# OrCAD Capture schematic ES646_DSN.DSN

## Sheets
1 INDEX
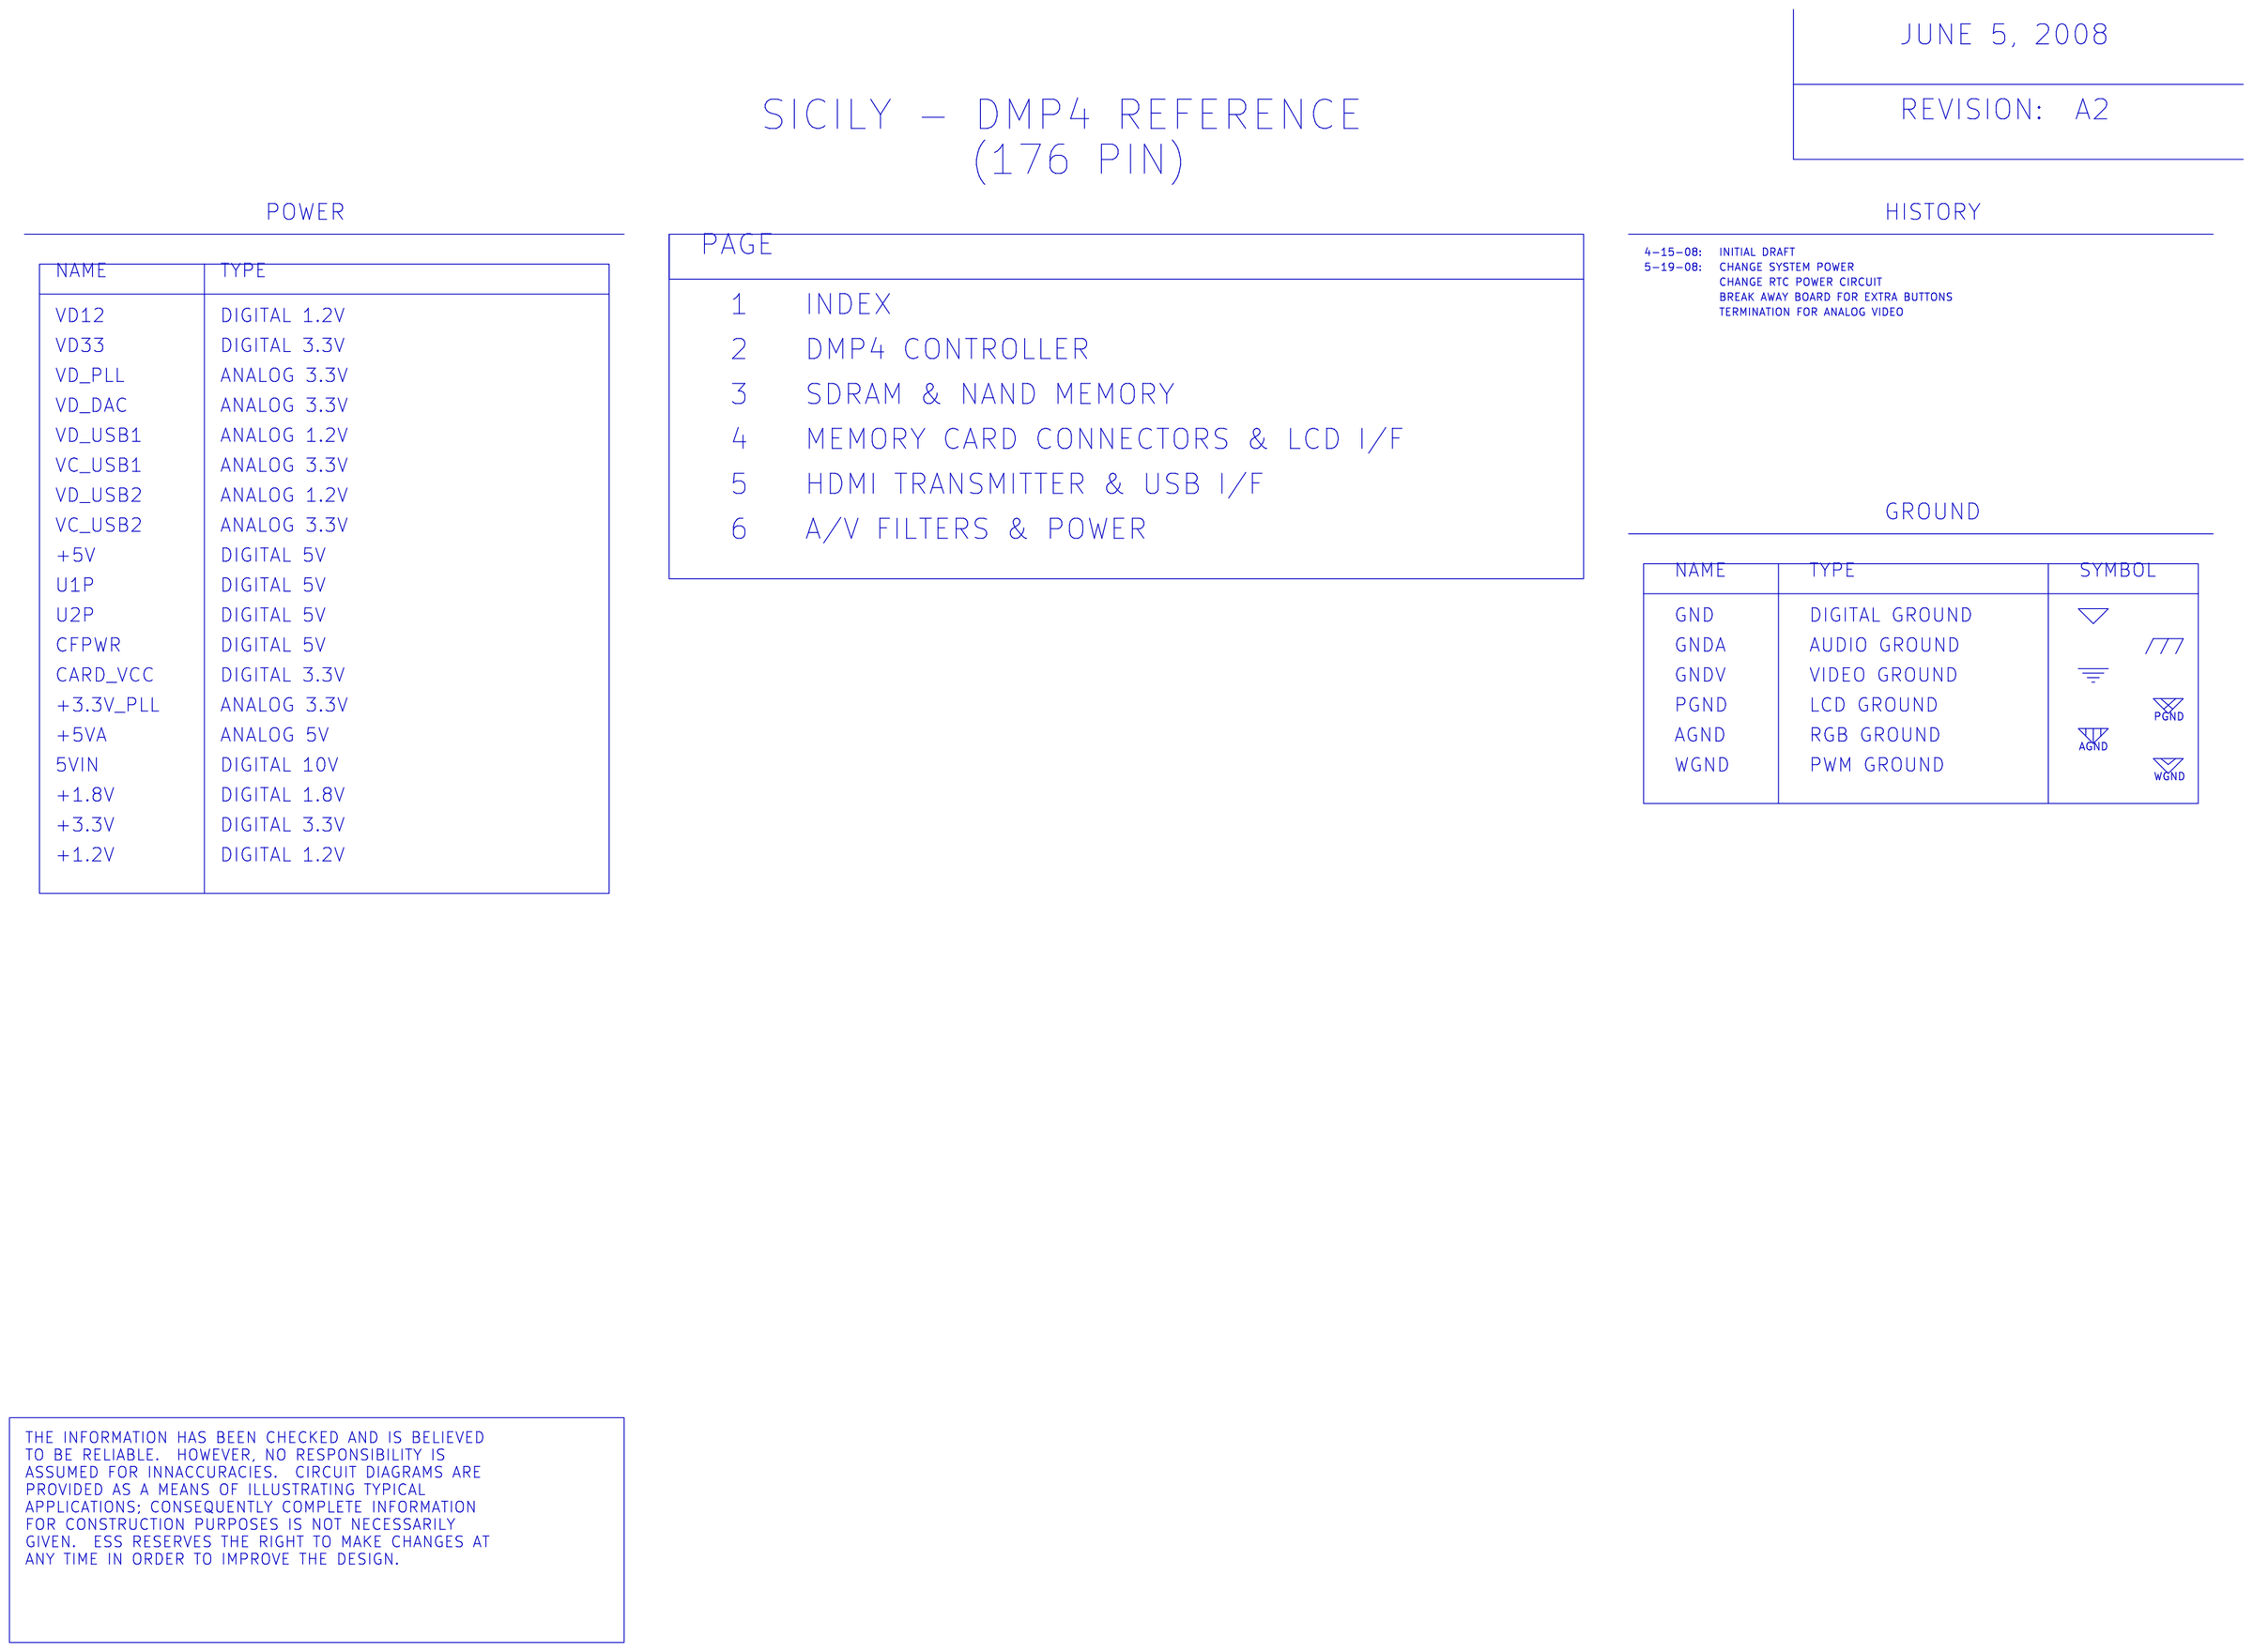
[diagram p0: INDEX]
2 DMP4(ES6461): size Custom
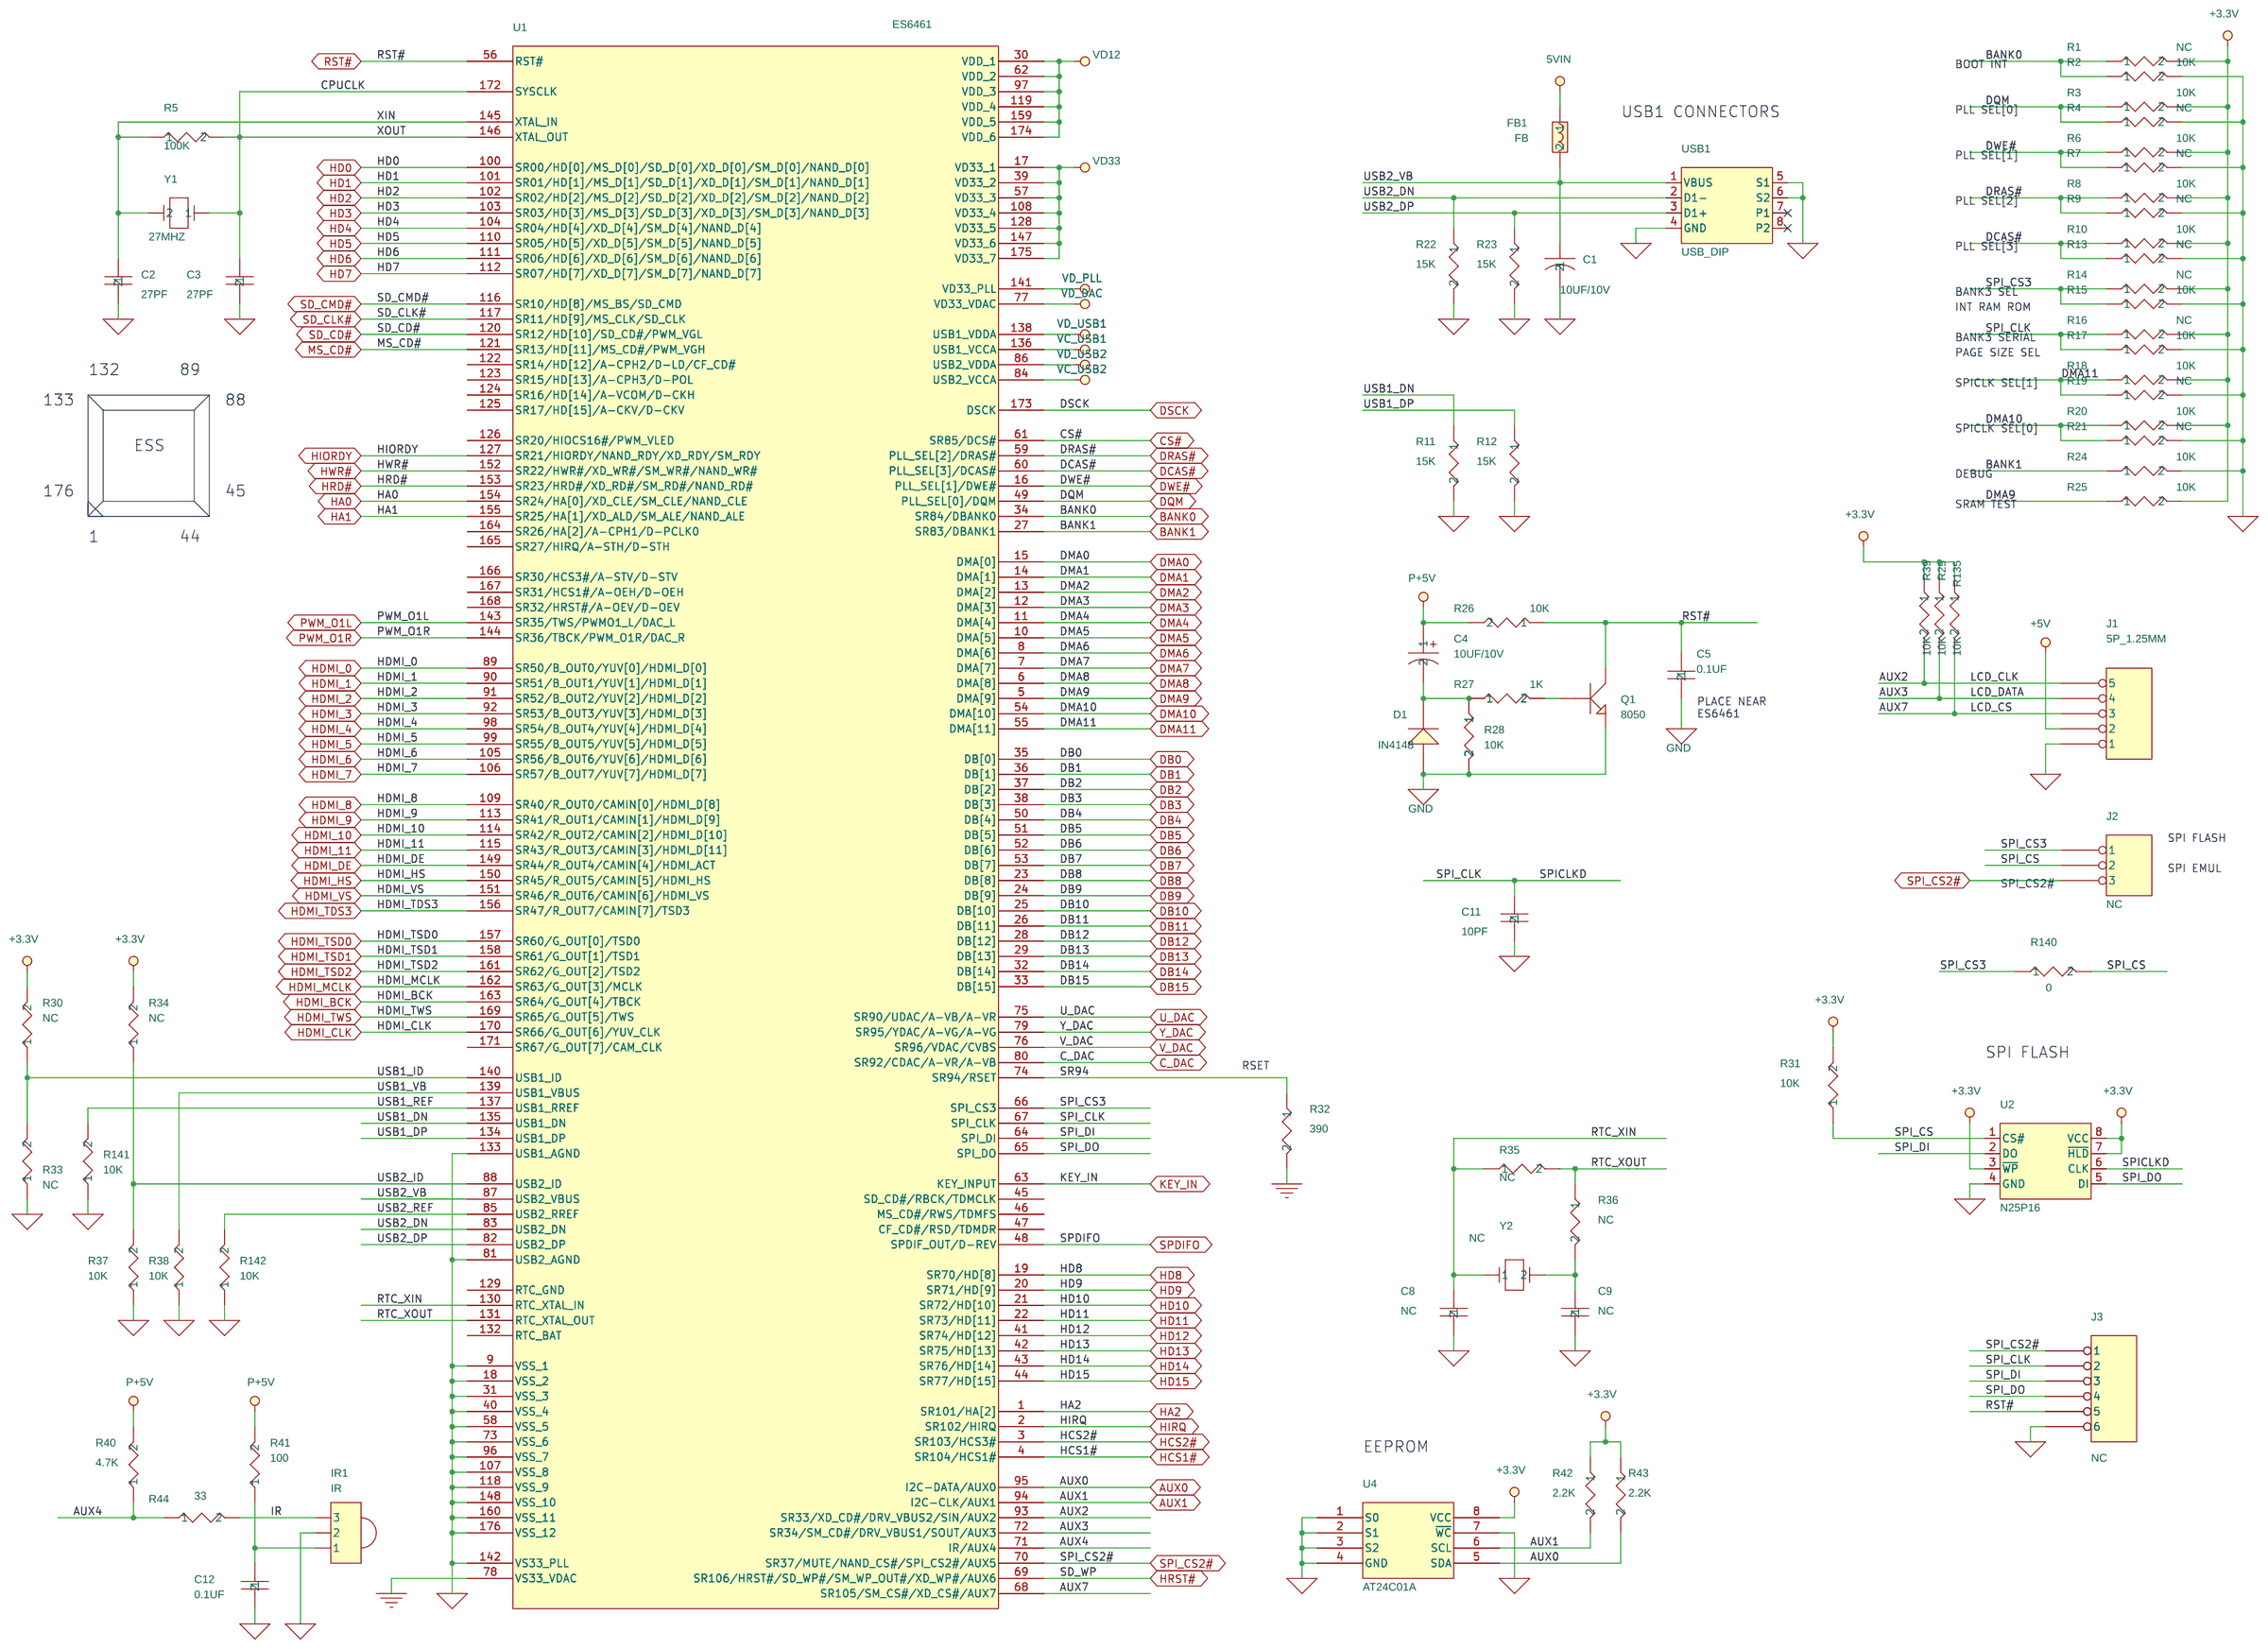
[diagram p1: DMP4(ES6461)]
3 MEMORY/CARD/KEY: size Custom
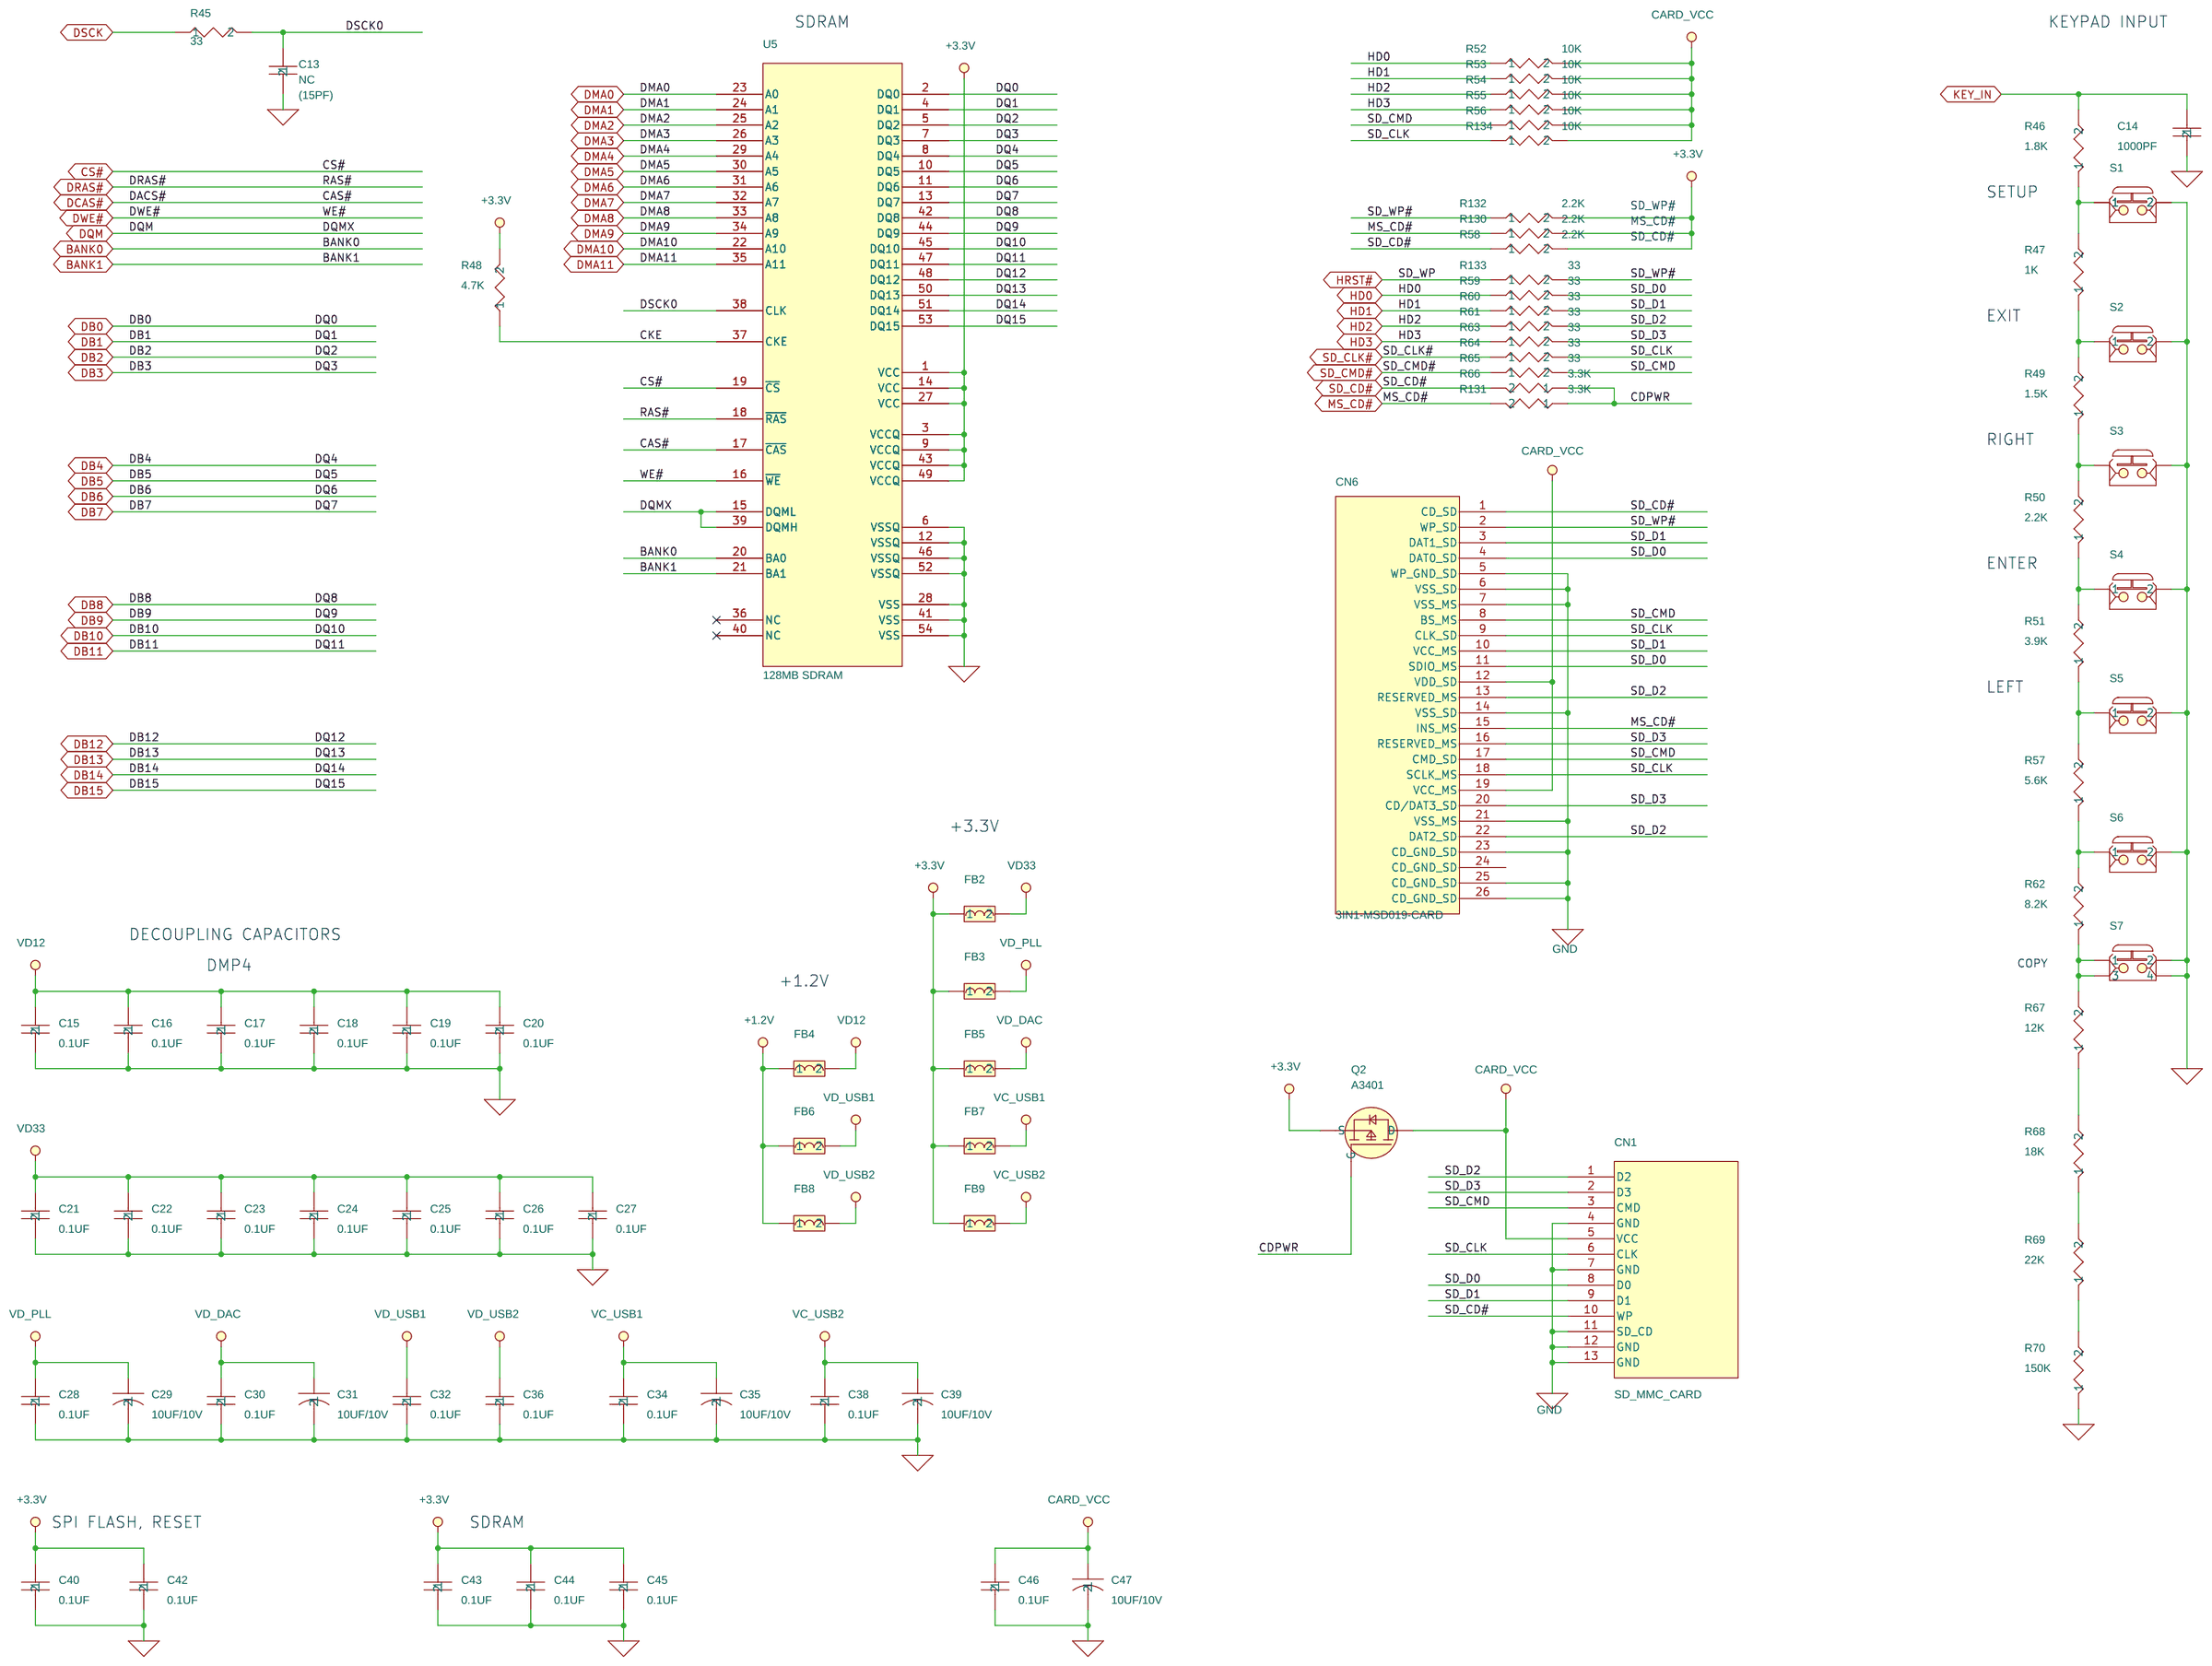
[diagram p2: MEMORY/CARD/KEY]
4 GL830: size B
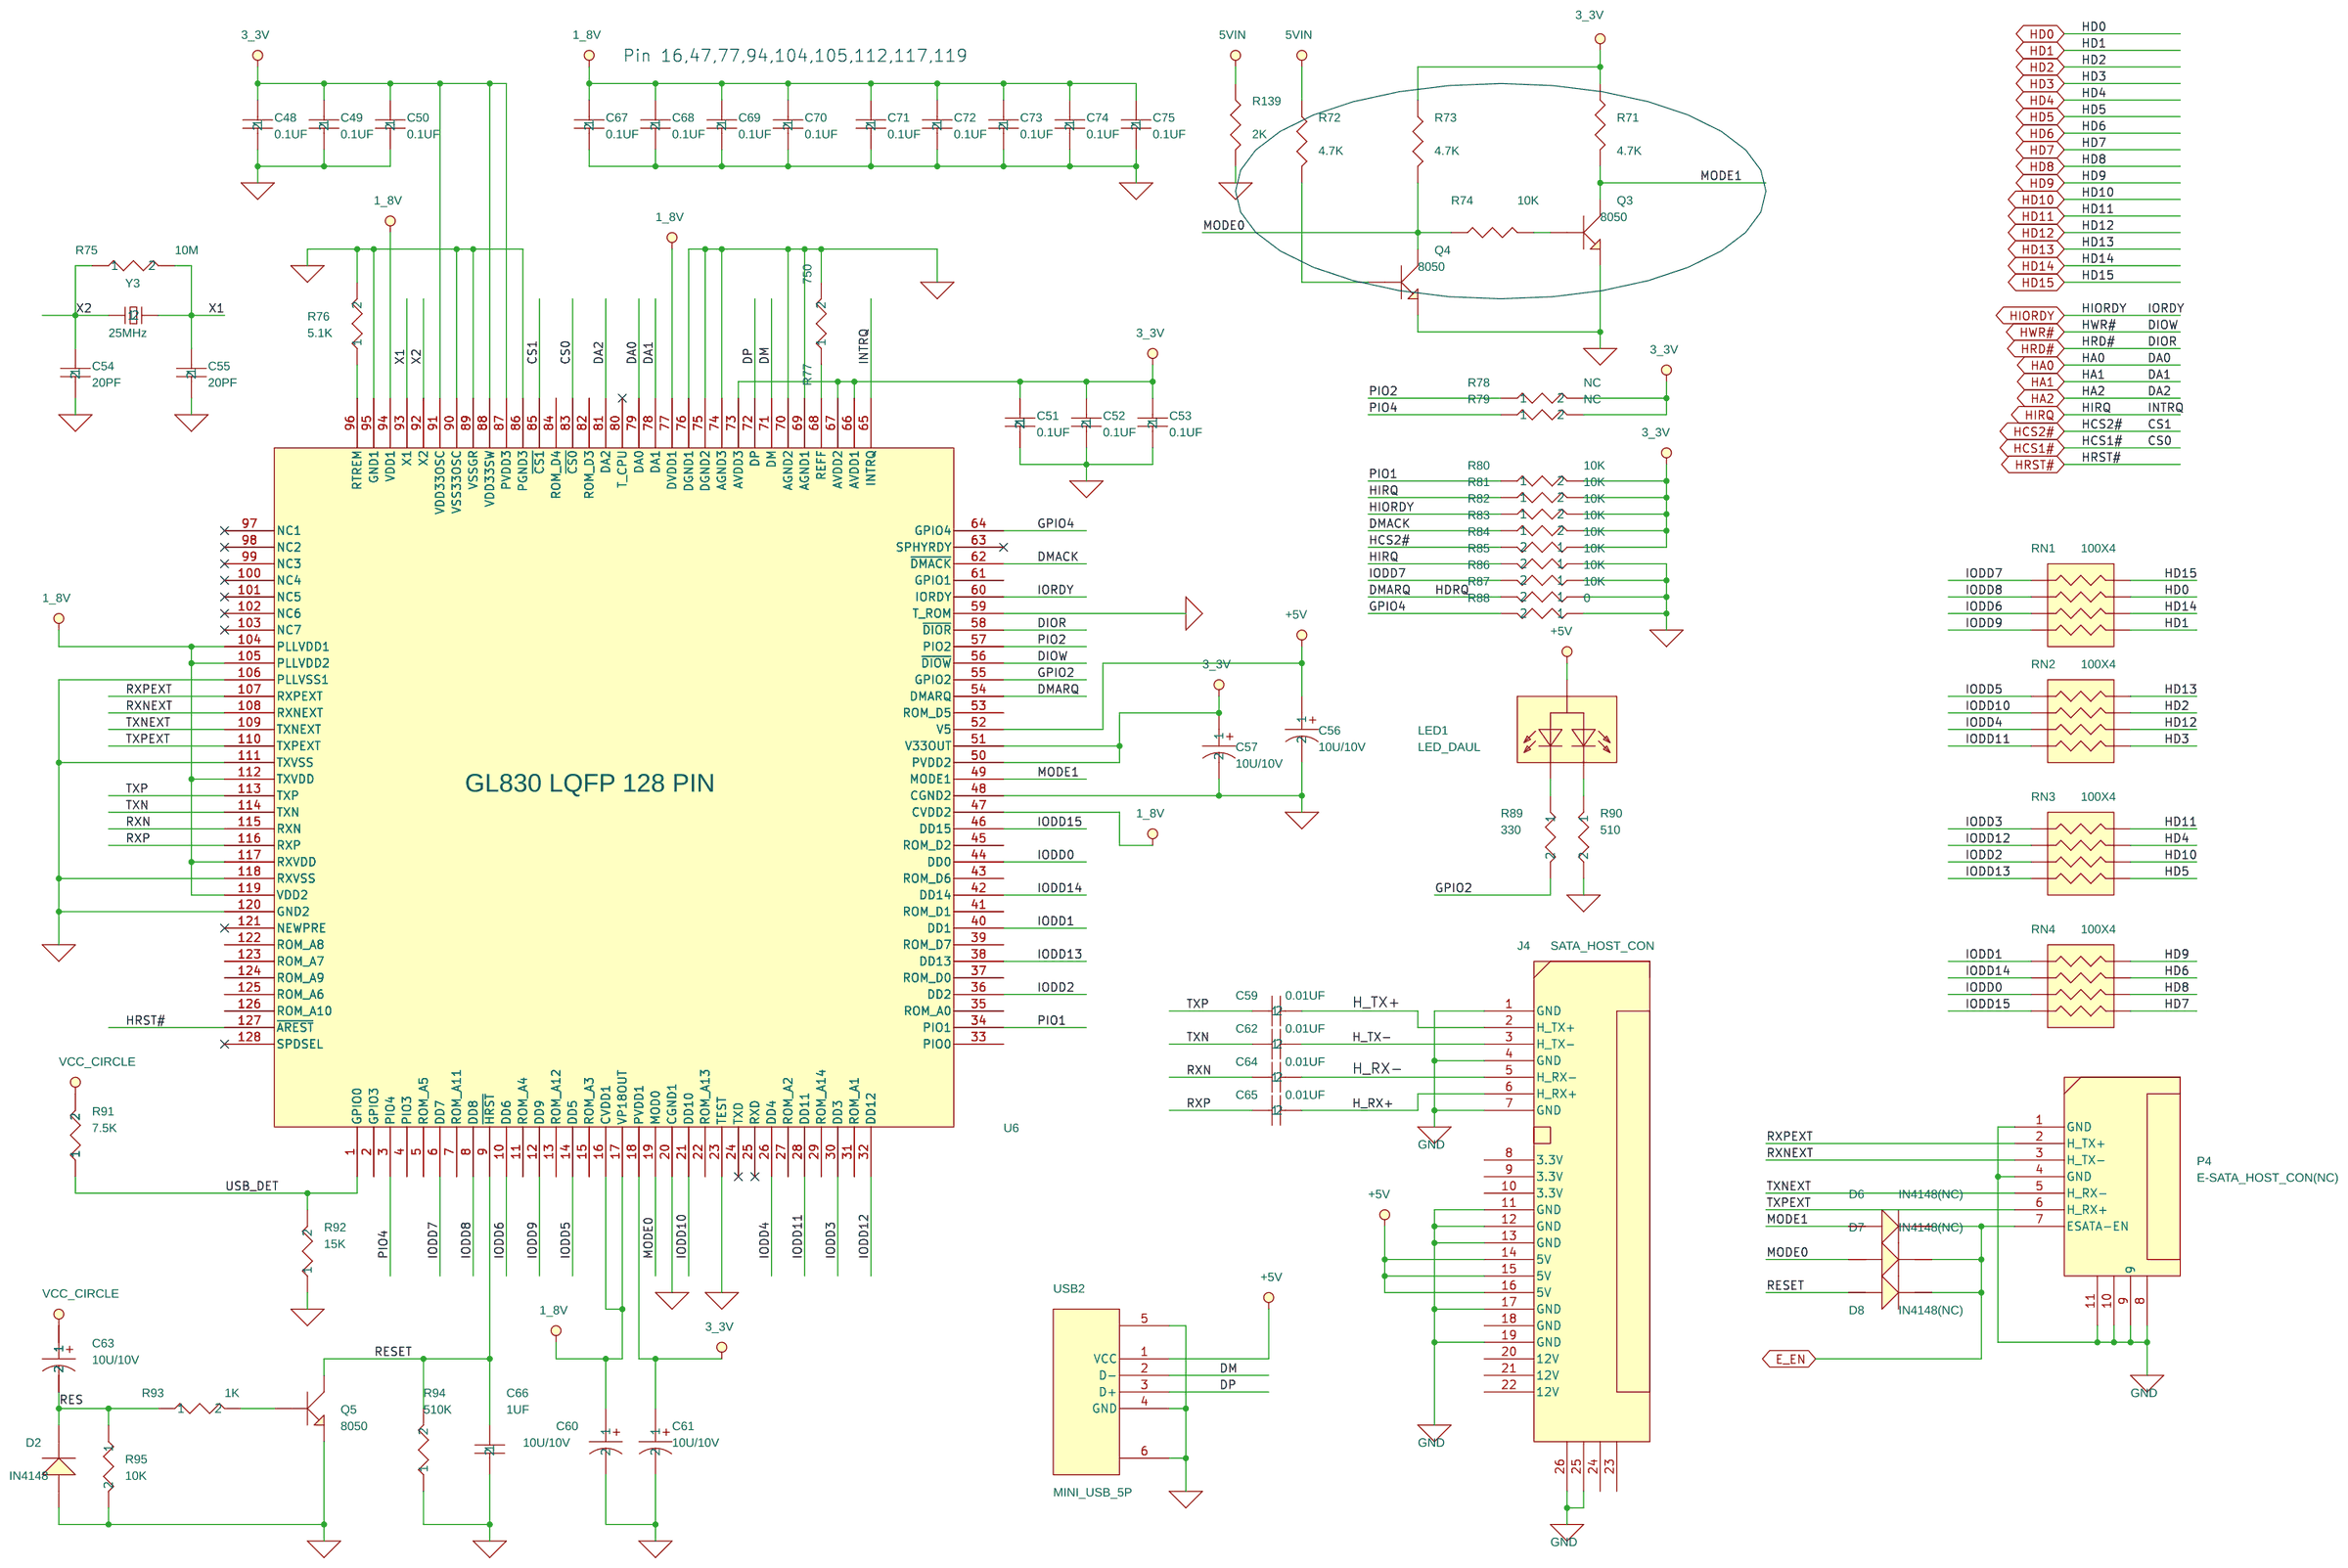
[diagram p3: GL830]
5 HDMI(CKD180): size B
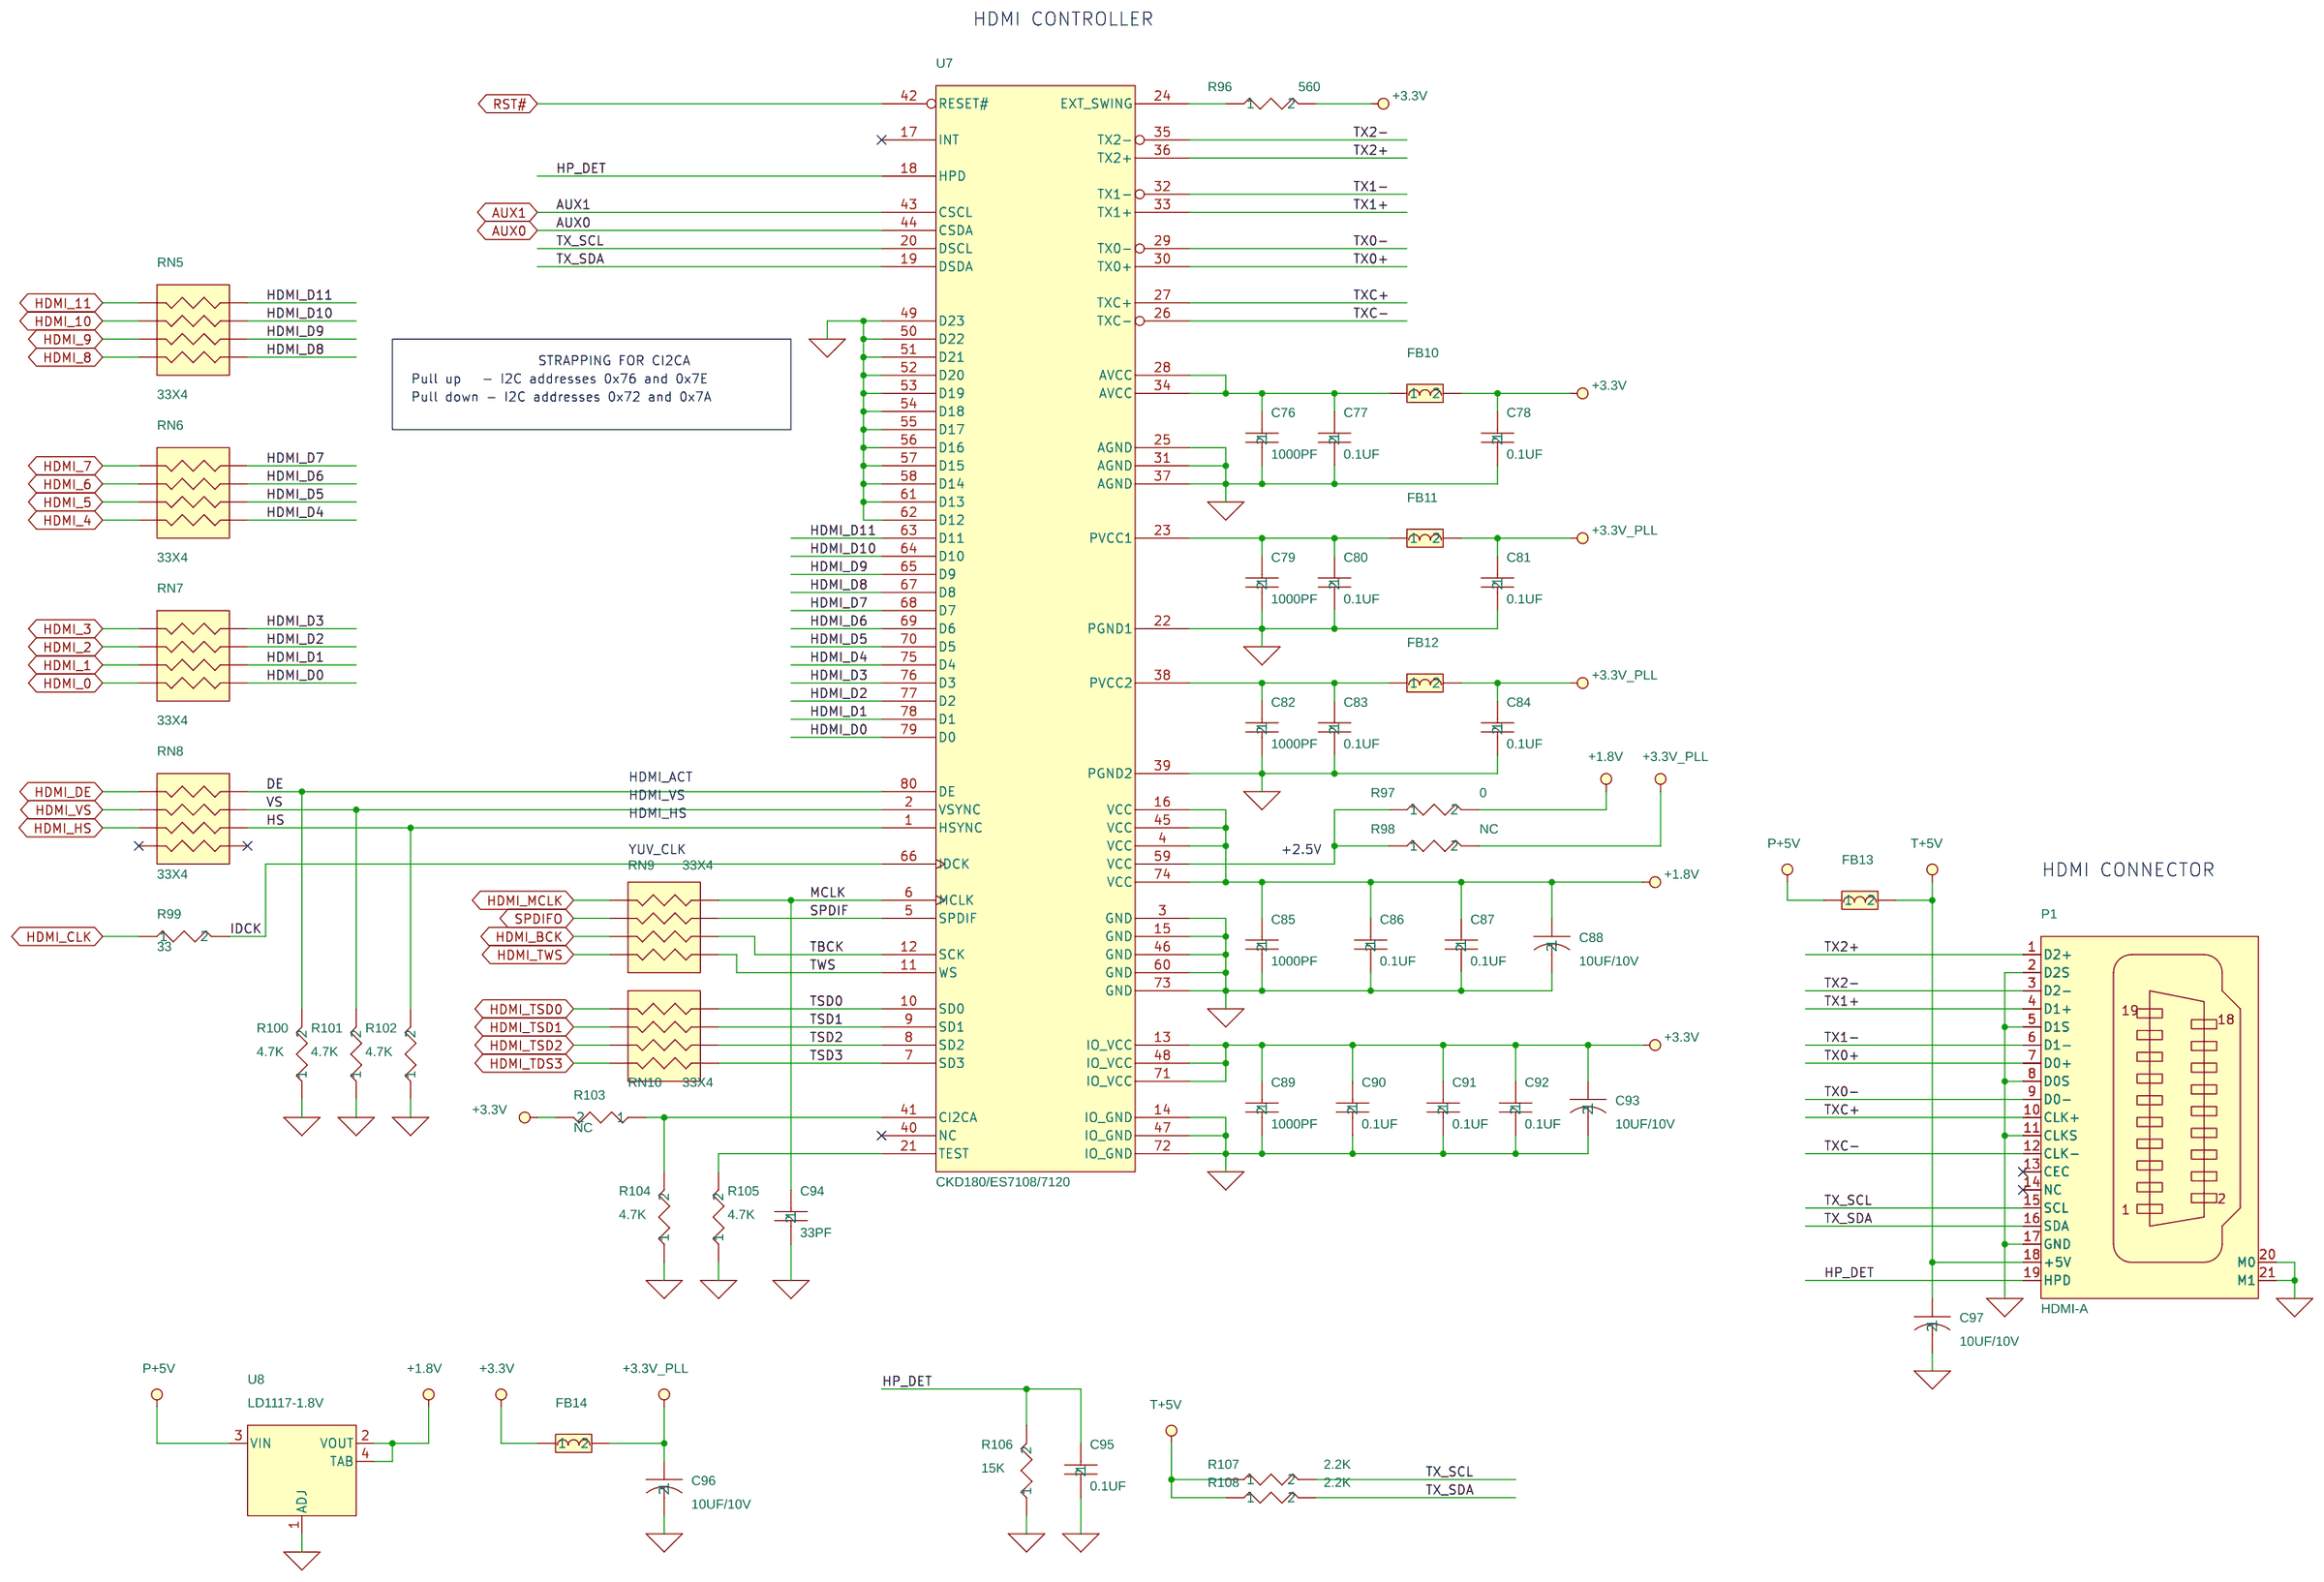
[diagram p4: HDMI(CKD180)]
6 POWER/AV OUT: size Custom
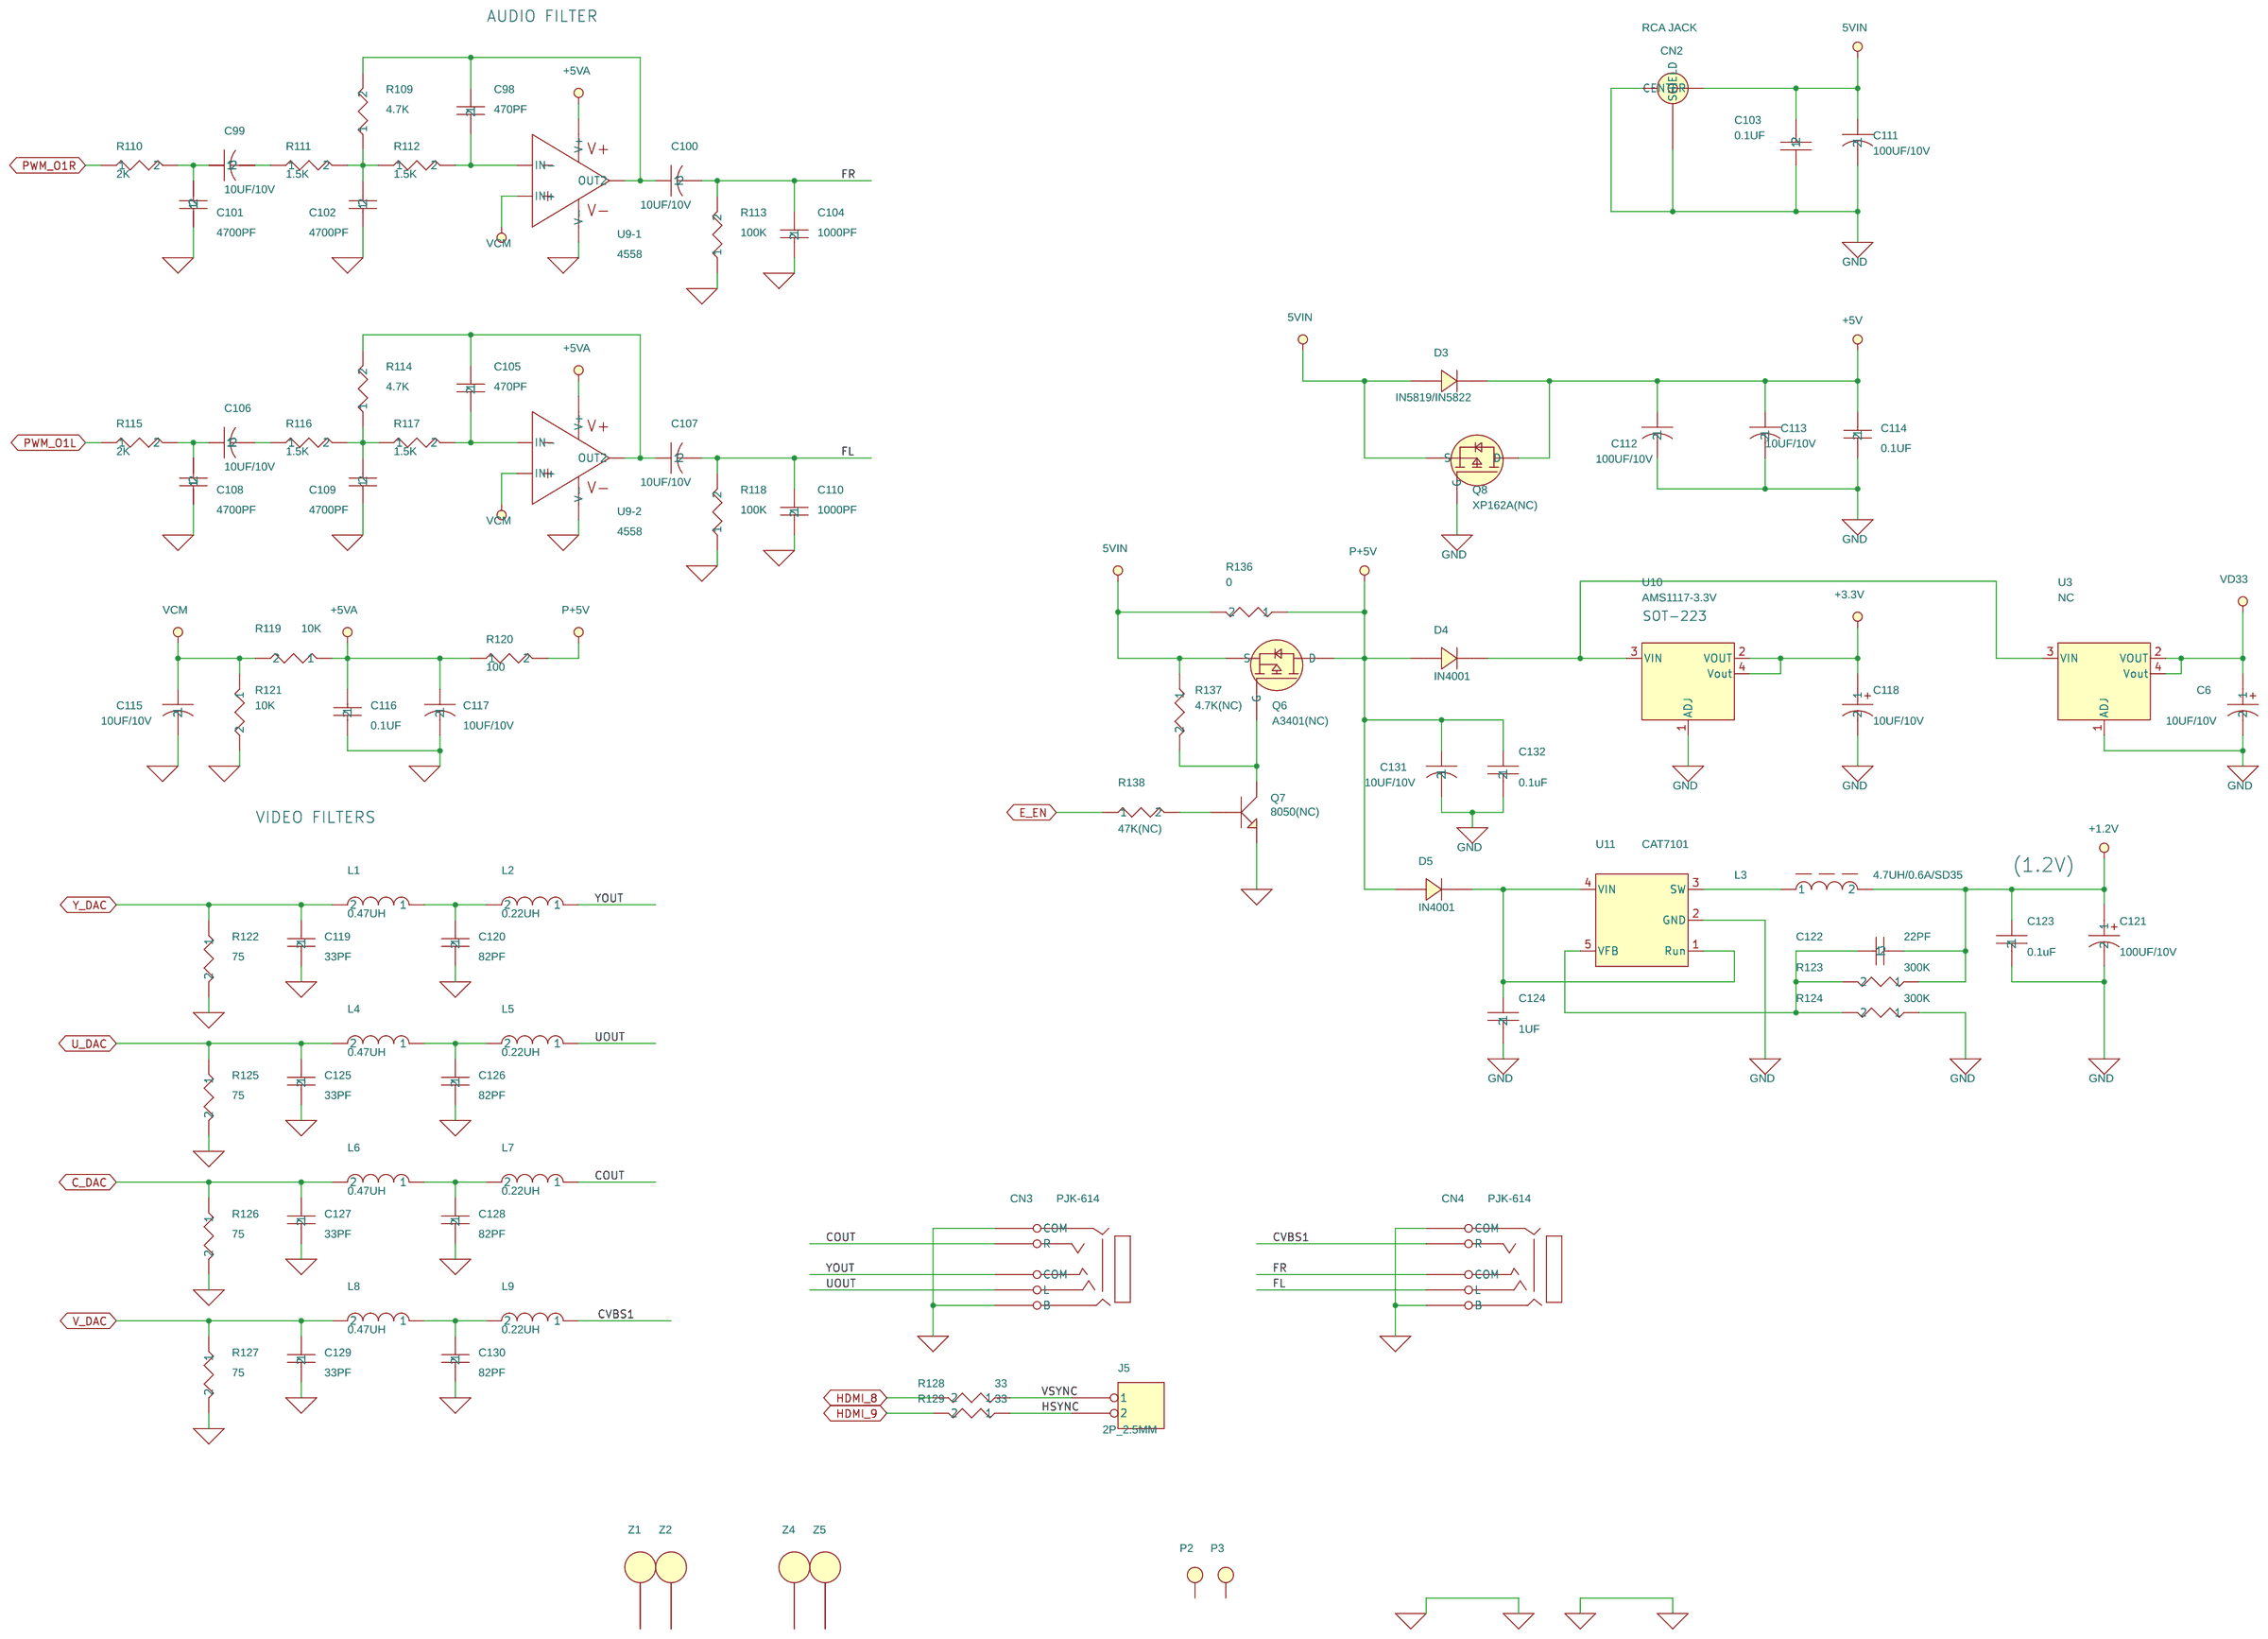
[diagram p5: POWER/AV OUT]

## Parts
sheet DMP4(ES6461)
C1  10UF/10V  [TAJA]
C2  27PF  [0603-CAP]
C3  27PF  [0603-CAP]
C4  10UF/10V  [TAJA]
C5  0.1UF  [0603-CAP]
C8  NC  [0603-CAP]
C9  NC  [0603-CAP]
C11  10PF  [0603-CAP]
C12  0.1UF  [0603-CAP]
D1  IN4148  [IN4148]
FB1  FB  [0603-FBR]
IR1  IR  [IR1]
J1  5P_1.25MM  [CON5/1.25S]
J2  NC  [CON2.0-3]
J3  NC  [CON2.0-6]
Q1  8050  [SOT-23]
R1  NC  [0603-RES]
R2  10K  [0603-RES]
R3  10K  [0603-RES]
R4  NC  [0603-RES]
R5  100K  [0603-RES]
R6  10K  [0603-RES]
R7  NC  [0603-RES]
R8  10K  [0603-RES]
R9  NC  [0603-RES]
R10  10K  [0603-RES]
R11  15K  [0603-RES]
R12  15K  [0603-RES]
R13  NC  [0603-RES]
R14  NC  [0603-RES]
R15  10K  [0603-RES]
R16  NC  [0603-RES]
R17  10K  [0603-RES]
R18  10K  [0603-RES]
R19  NC  [0603-RES]
R20  10K  [0603-RES]
R21  NC  [0603-RES]
R22  15K  [0603-RES]
R23  15K  [0603-RES]
R24  10K  [0603-RES]
R25  10K  [0603-RES]
R26  10K  [0603-RES]
R27  1K  [0603-RES]
R28  10K  [0603-RES]
R29  10K  [0603-RES]
R30  NC  [0603-RES]
R31  10K  [0603-RES]
R32  390  [0603-RES]
R33  NC  [0603-RES]
R34  NC  [0603-RES]
R35  NC  [0603-RES]
R36  NC  [0603-RES]
R37  10K  [0603-RES]
R38  10K  [0603-RES]
R39  10K  [0603-RES]
R40  4.7K  [0603-RES]
R41  100  [0603-RES]
R42  2.2K  [0603-RES]
R43  2.2K  [0603-RES]
R44  33  [0603-RES]
R135  10K  [0603-RES]
R140  0  [0603-RES]
R141  10K  [0603-RES]
R142  10K  [0603-RES]
U1  ES6461  [LQFP176/ES6811]
U2  N25P16  [M25P80]
U4  AT24C01A  [SO-8]
USB1  USB_DIP  [USB-A]
Y1  27MHZ  [HC-49/SM]
Y2  NC  [32.768KHZ-SMT]
sheet GL830
C48  0.1UF  [0603-CAP]
C49  0.1UF  [0603-CAP]
C50  0.1UF  [0603-CAP]
C51  0.1UF  [0603-CAP]
C52  0.1UF  [0603-CAP]
C53  0.1UF  [0603-CAP]
C54  20PF  [0603-CAP]
C55  20PF  [0603-CAP]
C56  10U/10V  [TAJA]
C57  10U/10V  [TAJA]
C59  0.01UF  [0603-CAP]
C60  10U/10V  [TAJA]
C61  10U/10V  [TAJA]
C62  0.01UF  [0603-CAP]
C63  10U/10V  [TAJA]
C64  0.01UF  [0603-CAP]
C65  0.01UF  [0603-CAP]
C66  1UF  [0603-CAP]
C67  0.1UF  [0603-CAP]
C68  0.1UF  [0603-CAP]
C69  0.1UF  [0603-CAP]
C70  0.1UF  [0603-CAP]
C71  0.1UF  [0603-CAP]
C72  0.1UF  [0603-CAP]
C73  0.1UF  [0603-CAP]
C74  0.1UF  [0603-CAP]
C75  0.1UF  [0603-CAP]
D2  IN4148  [IN4148]
D6  IN4148(NC)  [IN4148-LYH]
D7  IN4148(NC)  [IN4148-LYH]
D8  IN4148(NC)  [IN4148-LYH]
J4  SATA_HOST_CON  [SATA2.5HDD-LYH-SMT-A]
LED1  LED_DAUL  [LED2A]
P4  E-SATA_HOST_CON(NC)  [E-SATA-1.27A]
Q3  8050  [SOT23]
Q4  8050  [SOT23]
Q5  8050  [SOT-23]
R71  4.7K  [0603-RES]
R72  4.7K  [0603-RES]
R73  4.7K  [0603-RES]
R74  10K  [0603-RES]
R75  10M  [0603-RES]
R76  5.1K  [0603-RES]
R77  750  [0603-RES]
R78  NC  [0603-RES]
R79  NC  [0603-RES]
R80  10K  [0603-RES]
R81  10K  [0603-RES]
R82  10K  [0603-RES]
R83  10K  [0603-RES]
R84  10K  [0603-RES]
R85  10K  [0603-RES]
R86  10K  [0603-RES]
R87  10K  [0603-RES]
R88  0  [0603-RES]
R89  330  [0603-RES]
R90  510  [0603-RES]
R91  7.5K  [0603-RES]
R92  15K  [0603-RES]
R93  1K  [0603-RES]
R94  510K  [0603-RES]
R95  10K  [0603-RES]
R139  2K  [0603-RES]
RN1  100X4  [RP4-065W-C]
RN2  100X4  [RP4-065W-C]
RN3  100X4  [RP4-065W-C]
RN4  100X4  [RP4-065W-C]
U6  GL830 LQFP 128 PIN  [GL830]
USB2  MINI_USB_5P  [SUBAA]
Y3  25MHz  [HC-49/SM]
sheet HDMI(CKD180)
C76  1000PF  [0603-CAP]
C77  0.1UF  [0603-CAP]
C78  0.1UF  [0603-CAP]
C79  1000PF  [0603-CAP]
C80  0.1UF  [0603-CAP]
C81  0.1UF  [0603-CAP]
C82  1000PF  [0603-CAP]
C83  0.1UF  [0603-CAP]
C84  0.1UF  [0603-CAP]
C85  1000PF  [0603-CAP]
C86  0.1UF  [0603-CAP]
C87  0.1UF  [0603-CAP]
C88  10UF/10V  [TAJA]
C89  1000PF  [0603-CAP]
C90  0.1UF  [0603-CAP]
C91  0.1UF  [0603-CAP]
C92  0.1UF  [0603-CAP]
C93  10UF/10V  [TAJA]
C94  33PF  [0603-CAP]
C95  0.1UF  [0603-CAP]
C96  10UF/10V  [TAJA]
C97  10UF/10V  [TAJA]
FB10  FB  [0603-FBR]
FB11  FB  [0603-FBR]
FB12  FB  [0603-FBR]
FB13  FB  [0603-FBR]
FB14  FB  [0603-FBR]
P1  HDMI-A  [HDMI-CON-HOLE]
R96  560  [0603-RES]
R97  0  [0603-RES]
R98  NC  [0603-RES]
R99  33  [0603-RES]
R100  4.7K  [0603-RES]
R101  4.7K  [0603-RES]
R102  4.7K  [0603-RES]
R103  NC  [0603-RES]
R104  4.7K  [0603-RES]
R105  4.7K  [0603-RES]
R106  15K  [0603-RES]
R107  2.2K  [0603-RES]
R108  2.2K  [0603-RES]
RN5  33X4  [RP4-065W-C]
RN6  33X4  [RP4-065W-C]
RN7  33X4  [RP4-065W-C]
RN8  33X4  [RP4-065W-C]
RN9  33X4  [RP4-065W-C]
RN10  33X4  [RP4-065W-C]
U7  CKD180/ES7108/7120  [SIL9030/ES7120]
U8  LD1117-1.8V  [SOT-223]
sheet MEMORY/CARD/KEY
C13  NC  [0603-CAP]
C14  1000PF  [0603-CAP]
C15  0.1UF  [0603-CAP]
C16  0.1UF  [0603-CAP]
C17  0.1UF  [0603-CAP]
C18  0.1UF  [0603-CAP]
C19  0.1UF  [0603-CAP]
C20  0.1UF  [0603-CAP]
C21  0.1UF  [0603-CAP]
C22  0.1UF  [0603-CAP]
C23  0.1UF  [0603-CAP]
C24  0.1UF  [0603-CAP]
C25  0.1UF  [0603-CAP]
C26  0.1UF  [0603-CAP]
C27  0.1UF  [0603-CAP]
C28  0.1UF  [0603-CAP]
C29  10UF/10V  [TAJA]
C30  0.1UF  [0603-CAP]
C31  10UF/10V  [TAJA]
C32  0.1UF  [0603-CAP]
C34  0.1UF  [0603-CAP]
C35  10UF/10V  [TAJA]
C36  0.1UF  [0603-CAP]
C38  0.1UF  [0603-CAP]
C39  10UF/10V  [TAJA]
C40  0.1UF  [0603-CAP]
C42  0.1UF  [0603-CAP]
C43  0.1UF  [0603-CAP]
C44  0.1UF  [0603-CAP]
C45  0.1UF  [0603-CAP]
C46  0.1UF  [0603-CAP]
C47  10UF/10V  [TAJA]
CN1  SD_MMC_CARD  [2IN1_CARD]
CN6  3IN1-MSD019-CARD  [3IN1-MSD019]
FB2  FB  [0603-FBR]
FB3  FB  [0603-FBR]
FB4  FB  [0603-FBR]
FB5  FB  [0603-FBR]
FB6  NC  [0603-FBR]
FB7  FB  [0603-FBR]
FB8  NC  [0603-FBR]
FB9  FB  [0603-FBR]
Q2  A3401  [SOT-23]
R45  33  [0603-RES]
R46  1.8K  [0603-RES]
R47  1K  [0603-RES]
R48  4.7K  [0603-RES]
R49  1.5K  [0603-RES]
R50  2.2K  [0603-RES]
R51  3.9K  [0603-RES]
R52  10K  [0603-RES]
R53  10K  [0603-RES]
R54  10K  [0603-RES]
R55  10K  [0603-RES]
R56  10K  [0603-RES]
R57  5.6K  [0603-RES]
R58  2.2K  [0603-RES]
R59  33  [0603-RES]
R60  33  [0603-RES]
R61  33  [0603-RES]
R62  8.2K  [0603-RES]
R63  33  [0603-RES]
R64  33  [0603-RES]
R65  33  [0603-RES]
R66  3.3K  [0603-RES]
R67  12K  [0603-RES]
R68  18K  [0603-RES]
R69  22K  [0603-RES]
R70  150K  [0603-RES]
R130  2.2K  [0603-RES]
R131  3.3K  [0603-RES]
R132  2.2K  [0603-RES]
R133  33  [0603-RES]
R134  10K  [0603-RES]
S1  SW PB  [ANJIANC]
S2  SW PB  [ANJIANC]
S3  SW PB  [ANJIANC]
S4  SW PB  [ANJIANC]
S5  SW PB  [ANJIANC]
S6  SW PB  [ANJIANC]
S7  SW PB  [BUT]
U5  128MB SDRAM  [TSOP54]
sheet POWER/AV OUT
C6  10UF/10V  [TAJA]
C98  470PF  [0603-CAP]
C99  10UF/10V  [TAJA]
C100  10UF/10V  [TAJA]
C101  4700PF  [0603-CAP]
C102  4700PF  [0603-CAP]
C103  0.1UF  [0603-CAP]
C104  1000PF  [0603-CAP]
C105  470PF  [0603-CAP]
C106  10UF/10V  [TAJA]
C107  10UF/10V  [TAJA]
C108  4700PF  [0603-CAP]
C109  4700PF  [0603-CAP]
C110  1000PF  [0603-CAP]
C111  100UF/10V  [CE6X11]
C112  100UF/10V  [EC]
C113  10UF/10V  [TAJA]
C114  0.1UF  [0603-CAP]
C115  10UF/10V  [TAJA]
C116  0.1UF  [0603-CAP]
C117  10UF/10V  [TAJA]
C118  10UF/10V  [TAJA]
C119  33PF  [0603-CAP]
C120  82PF  [0603-CAP]
C121  100UF/10V  [EC]
C122  22PF  [0603-CAP]
C123  0.1uF  [0603-CAP]
C124  1UF  [0603-CAP]
C125  33PF  [0603-CAP]
C126  82PF  [0603-CAP]
C127  33PF  [0603-CAP]
C128  82PF  [0603-CAP]
C129  33PF  [0603-CAP]
C130  82PF  [0603-CAP]
C131  10UF/10V  [TAJA]
C132  0.1uF  [0603-CAP]
CN2  RCA JACK  [GM-POW-A]
CN3  PJK-614  [PHONE]
CN4  PJK-614  [PHONE]
D3  IN5819/IN5822  [SMBA]
D4  IN4001  [SMBA]
D5  IN4001  [SMBA]
J5  2P_2.5MM  [CON\1X2PS]
L1  0.47UH  [0603-FBR]
L2  0.22UH  [0603-FBR]
L3  4.7UH/0.6A/SD35  [SD35]
L4  0.47UH  [0603-FBR]
L5  0.22UH  [0603-FBR]
L6  0.47UH  [0603-FBR]
L7  0.22UH  [0603-FBR]
L8  0.47UH  [0603-FBR]
L9  0.22UH  [0603-FBR]
P2  T POINT R  [SANYOFMT]
P3  T POINT R  [SANYOFMT]
Q6  A3401(NC)  [SOT23]
Q7  8050(NC)  [SOT23]
Q8  XP162A(NC)  [SOT-89]
R109  4.7K  [0603-RES]
R110  2K  [0603-RES]
R111  1.5K  [0603-RES]
R112  1.5K  [0603-RES]
R113  100K  [0603-RES]
R114  4.7K  [0603-RES]
R115  2K  [0603-RES]
R116  1.5K  [0603-RES]
R117  1.5K  [0603-RES]
R118  100K  [0603-RES]
R119  10K  [0603-RES]
R120  100  [0603-RES]
R121  10K  [0603-RES]
R122  75  [0603-RES]
R123  300K  [0603-RES]
R124  300K  [0603-RES]
R125  75  [0603-RES]
R126  75  [0603-RES]
R127  75  [0603-RES]
R128  33  [0603-RES]
R129  33  [0603-RES]
R136  0  [0603-RES]
R137  4.7K(NC)  [0603-RES]
R138  47K(NC)  [0603-RES]
U3  NC  [AMS1117]
U9  4558  [SO-8]  (sections -1,-2)
U10  AMS1117-3.3V  [AMS1117]
U11  CAT7101  [V6300A]
Z1  PAD  [PAABAAACAABAABBA]
Z2  PAD  [PAABAAACAABAABBA]
Z4  PAD  [ZZMTH1]
Z5  PAD  [ZZMTH1]

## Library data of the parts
C1 C47 C93 C107 = CAP
C2 C40 C70 C78 C98 = CAP_NP_6
C3 C19 C48 C94 C102 = CAP_NP_3
C4 C57 = CAPACITOR_POL
C5 C28 C73 C80 C119 = CAP_NP_1
C8 C42 C52 C89 C130 = CAP_NP_2
C9 C30 C50 C76 C109 = CAP_NP_4
C11 C17 C69 C81 C101 = CAP_NP
C12 C43 C62 C90 C128 = CAP_NP_5
D1 D2 = DIODE_0
FB1 = FB: Real Value: (FB)
IR1 = CON3_0
J1 = HEADER_4_8
J2 = HEADER_3
J3 = HEADER_6
Q1 Q5 = NPN_1
R1 = R_15: Real Value: (10K)
R2 R68 R93 R121 = R_16
R3 = R_47
R4 = R_42: Real Value: (10K)
R5 R60 R75 R129 = R_19
R6 R89 R100 R126 R131 = R_3
R7 = R_2: Real Value: (10K)
R8 R56 R81 R107 R111 = R_8
R9 = R_5: Real Value: (10K)
R10 R67 R78 R120 = R_13
R11 = R_33
R12 = R_40
R13 = R_10: Real Value: (10K)
R14 = R_39
R15 = R_35: Real Value: (10K)
R16 = R_18: Real Value: (10K)
R17 R48 R128 = R_21
R18 R59 R122 = R_22
R19 = R_27: Real Value: (4.7K)
R20 = R_31
R21 = R_34: Real Value: (4.7K)
R22 = R_45
R23 R57 R84 R97 R109 = R_4
R24 = R_41
R25 = R_38
R26 R61 R92 R103 R137 = R_1
R27 R46 = R_30
R28 R47 R76 R108 R116 = R_9
R29 R58 = R_29
R30 R87 R99 R117 R134 = R_7
R31 R69 R77 R102 R125 = R
R32 = R_46
R33 R53 R79 R136 = R_20
R34 = R_36
R35 R64 = R_25
R36 R88 R124 R130 = R_17
R37 R51 R80 R96 R110 = R_6
R38 = R_32
R39 = R_37
R40 R55 R113 = R_23
R41 R49 = R_28
R42 R45 R91 R104 R114 = R_12
R43 R65 R94 R118 = R_14
R44 R52 = R_26
R135 = R_44
R70 R140 = R_24
R141 = R_43
R50 R85 R105 R112 R142 = R_11
U1 = DMP4_176
U2 = N25P16_0
U4 = 24C01A
USB1 = USB_CONN_2
Y1 = CRYSTAL_v2_1
Y2 = CRYSTAL_v2
C24 C49 C92 C104 = CAP_NP_17
C38 C51 = CAP_NP_20
C32 C53 C95 C126 = CAP_NP_8
C34 C54 C82 C116 = CAP_NP_14
C36 C55 C120 = CAP_NP_18
C56 = CAPACITOR_POL_3
C14 C59 C79 C129 = CAP_NP_16
C60 = CAPACITOR_POL_2
C61 = CAPACITOR_POL_1
C63 = CAPACITOR_POL_4
C64 C87 C125 = CAP_NP_10
C44 C65 C77 C108 = CAP_NP_9
C25 C66 C84 C114 = CAP_NP_15
C46 C67 C85 C105 = CAP_NP_11
C26 C68 = CAP_NP_19
C45 C71 C86 C122 = CAP_NP_12
C20 C72 = CAP_NP_21
C21 C74 C91 C110 = CAP_NP_7
C22 C75 C83 C127 = CAP_NP_13
D6-D8 = DIODE_6
J4 = SATA_HOST_CON_0_v2
LED1 = LED_BI-COLOUR_2
P4 = SATA_HOST_CON_1
Q3 Q4 Q7 = NPN_0
R71-R74 R139 = R0603
R82 R119 R132 = R_15
R83 R115 R133 = R_18
R63 R86 R98 R138 = R_10
R62 R90 R101 R123 = R_2
R54 R95 R106 R127 = R_5
RN1-RN10 = RES_NETWORK
U6 = SKS-LQFP128-GLI8196-0_2
USB2 = USBB-A_0
Y3 = CRYSTAL
C29 C88 C106 = CAP_1
C35 C96 C99 = CAP_3
C31 C97 C111 = CAP_2
FB4 FB10 = FB_1
FB3 FB11 = FB_2
FB2 FB12 = FB_3
FB9 FB13 = FB_4
FB6 FB14 = FB
P1 = HDMI-A
U7 = ES7108
U8 = REG1117
C13 = CAP_NP_10: Real Value: (15PF)
C15 = CAP_NP_23
C16 = CAP_NP_25
C18 = CAP_NP_26
C23 = CAP_NP_22
C27 = CAP_NP_24
C39 C100 = CAP_4
CN1 = CON36_0: Value_bak: PROCONN_MSD019-X01-1X90
CN6 = CON36_1: Value_bak: PROCONN_MSD019-X01-1X90
FB5 = FB_6
FB7 = FB_7
FB8 = FB_5
Q2 Q8 = MOSFET_P-CHANNEL
R66 = R_27
S1 = SW_PUSHBUTTON_6: 1ST PART FIELD: K3S5; 2ND PART FIELD: FR
S2 = SW_PUSHBUTTON_7: 1ST PART FIELD: K3S5; 2ND PART FIELD: FR
S3 = SW_PUSHBUTTON_2: 1ST PART FIELD: K3S5; 2ND PART FIELD: FR
S4 = SW_PUSHBUTTON_3: 1ST PART FIELD: K3S5; 2ND PART FIELD: FR
S5 = SW_PUSHBUTTON_4: 1ST PART FIELD: K3S5; 2ND PART FIELD: FR
S6 = SW_PUSHBUTTON_5: 1ST PART FIELD: K3S5; 2ND PART FIELD: FR
S7 = SW_PUSHBUTTON_0: 1ST PART FIELD: K3S5; 2ND PART FIELD: FR
U5 = 64MB_SDRAM
C6 = CAPACITOR_POL: Device: DIP_CAP_D50-P20-H70_10U-PL
C103 = C_1
C112 = CAPACITOR_1
C113 = CAPACITOR_2
C115 = CAP_5
C117 = CAP_6
C118 = CAPACITOR_POL_1: Device: DIP_CAP_D50-P20-H70_10U-PL
C121 = CAPACITOR_POL_2: Device: DIP_CAP_D50-P20-H70_10U-PL
C123 = C_3: REAL VALUE: (1U)
C124 = C_2: REAL VALUE: (1U)
C131 = CAPACITOR
C132 = C: REAL VALUE: (1U)
CN2 = RCA_JACK_0
CN3 CN4 = PHONEJACK_STEREO_4: MANUFACT: SINGATRON; MANUFACT P/N: AJ403-4T-SMT
D3-D5 = 1N4148_2
J5 = HEADER_4_6
L1 = INDUCTOR_7
L2 = INDUCTOR
L3 = INDUCTOR_0: 1st Part Field: 1206; PCB Footprint_1: SOC-R; REAL VALUE: (FB,1.5A)
L4 = INDUCTOR_1
L5 = INDUCTOR_5
L6 = INDUCTOR_2
L7 = INDUCTOR_4
L8 = INDUCTOR_6
L9 = INDUCTOR_3
P2 P3 = T_POINT_R
Q6 = FDN338P_0
U3 U10 = REG1117_3
U9 = OPA2134UA
U11 = REG1117_0
Z1 Z2 Z4 Z5 = RCA_JACK_0_v2

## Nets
5VIN: C103.2 C111.1 CN2.1(CENTER) D3.1 FB1.1 Q6.2(S) Q8.2(S) R72.1 R136.2 R137.1 R139.1
+1.2V: C121.1 C122.2 C123.1 FB4.1 FB6.1 FB8.1 L3.2 R123.1
+1.8V: C85.1 C86.1 C87.1 C88.1 R97.2 U7.4(VCC) U7.16(VCC) U7.45(VCC) U7.74(VCC) U8.2(VOUT) U8.4(TAB)
+3.3V: C40.1 C42.1 C43.1 C44.1 C45.1 C78.1 C89.1 C90.1 C91.1 C92.1 C93.1 C118.1 FB2.1 FB3.1 FB5.1 FB7.1 FB9.1 FB10.2 FB14.1 Q2.2(S) R1.2 R3.2 R6.2 R8.2 R10.2 R14.2 R16.2 R18.2 R20.2 R25.2 R29.1 R30.2 R31.2 R34.2 R39.1 R42.1 R43.1 R48.2 R58.2 R96.2 R103.2 R130.2 R132.2 R135.1 U2.3(~{WP}) U2.7(~{HLD}) U2.8(VCC) U4.8(VCC) U5.1(VCC) U5.3(VCCQ) U5.9(VCCQ) U5.14(VCC) U5.27(VCC) U5.43(VCCQ) U5.49(VCCQ) U7.13(IO_VCC) U7.48(IO_VCC) U7.71(IO_VCC) U10.2(VOUT) U10.4(Vout)
+3.3V_PLL: C81.1 C84.1 C96.1 FB11.2 FB12.2 FB14.2 R98.2
+5V: C56.1 C63.1 C112.1 C113.1 C114.1 D3.2 J1.2 J4.14(5V) J4.15(5V) J4.16(5V) LED1.1 Q8.3(D) R91.2 U6.52(V5) USB2.1(VCC)
+5VA: C116.1 C117.1 R119.1 R120.1 U9.8(V+)
GND: C1.2 C2.2 C3.2 C5.2 C6.2 C8.2 C9.2 C11.2 C12.2 C13.2 C14.2 C15.2 C16.2 C17.2 C18.2 C19.2 C20.2 C21.2 C22.2 C23.2 C24.2 C25.2 C26.2 C27.2 C28.2 C29.2 C30.2 C31.2 C32.2 C34.2 C35.2 C36.2 C38.2 C39.2 C40.2 C42.2 C43.2 C44.2 C45.2 C46.2 C47.2 C48.2 C49.2 C50.2 C51.2 C52.2 C53.2 C54.2 C55.2 C56.2 C57.2 C60.2 C61.2 C66.2 C67.2 C68.2 C69.2 C70.2 C71.2 C72.2 C73.2 C74.2 C75.2 C76.2 C77.2 C78.2 C79.2 C80.2 C81.2 C82.2 C83.2 C84.2 C85.2 C86.2 C87.2 C88.2 C89.2 C90.2 C91.2 C92.2 C93.2 C94.2 C95.2 C96.2 C97.2 C101.1 C102.1 C103.1 C104.2 C108.1 C109.1 C110.2 C111.2 C112.2 C113.2 C114.2 C115.2 C116.2 C117.2 C118.2 C119.2 C120.2 C121.2 C123.2 C124.2 C125.2 C126.2 C127.2 C128.2 C129.2 C130.2 C131.2 C132.2 CN1.4(GND) CN1.7(GND) CN1.11(SD_CD) CN1.12(GND) CN1.13(GND) CN2.2(SHIELD) CN2.3 CN3.1(COM) CN3.8(B) CN4.1(COM) CN4.8(B) CN6.5(WP_GND_SD) CN6.6(VSS_SD) CN6.7(VSS_MS) CN6.14(VSS_SD) CN6.21(VSS_MS) CN6.23(CD_GND_SD) CN6.25(CD_GND_SD) CN6.26(CD_GND_SD) D1.1 D2.1 IR1.2 J1.1 J3.6 J4.1(GND) J4.4(GND) J4.7(GND) J4.11(GND) J4.12(GND) J4.13(GND) J4.17(GND) J4.19(GND) J4.25 J4.26 P1.2(D2S) P1.5(D1S) P1.8(D0S) P1.11(CLKS) P1.17(GND) P1.20(M0) P1.21(M1) P4.1(GND) P4.4(GND) P4.8 P4.9 P4.10 P4.11 Q1.2 Q3.2 Q4.2 Q5.2 Q7.2 Q8.1(G) R2.2 R4.2 R7.2 R9.2 R11.2 R12.2 R13.2 R15.2 R17.2 R19.2 R21.2 R22.2 R23.2 R24.2 R28.2 R32.2 R33.1 R37.1 R38.1 R70.1 R76.2 R77.2 R85.1 R86.1 R87.1 R88.1 R90.2 R92.1 R94.1 R95.2 R100.1 R101.1 R102.1 R104.1 R105.1 R106.1 R113.1 R118.1 R121.2 R122.2 R124.1 R125.2 R126.2 R127.2 R139.2 R141.1 R142.1 S1.2 S2.2 S3.2 S4.2 S5.2 S6.2 S7.2 S7.4 U1.9(VSS_1) U1.18(VSS_2) U1.31(VSS_3) U1.40(VSS_4) U1.58(VSS_5) U1.73(VSS_6) U1.78(VS33_VDAC) U1.81(USB2_AGND) U1.96(VSS_7) U1.107(VSS_8) U1.118(VSS_9) U1.133(USB1_AGND) U1.142(VS33_PLL) U1.148(VSS_10) U1.160(VSS_11) U1.176(VSS_12) U2.4(GND) U3.1(ADJ) U4.1(S0) U4.2(S1) U4.3(S2) U4.4(GND) U4.7(~{WC}) U5.6(VSSQ) U5.12(VSSQ) U5.28(VSS) U5.41(VSS) U5.46(VSSQ) U5.52(VSSQ) U5.54(VSS) U6.20(CGND1) U6.23(TEST) U6.48(CGND2) U6.59(T_ROM) U6.69(AGND1) U6.70(AGND2) U6.74(AGND3) U6.75(DGND2) U6.76(DGND1) U6.86(PGND3) U6.89(VSSGR) U6.90(VSS33OSC) U6.95(GND1) U6.106(PLLVSS1) U6.111(TXVSS) U6.118(RXVSS) U6.120(GND2) U7.3(GND) U7.14(IO_GND) U7.15(GND) U7.22(PGND1) U7.25(AGND) U7.31(AGND) U7.37(AGND) U7.39(PGND2) U7.46(GND) U7.47(IO_GND) U7.49(D23) U7.50(D22) U7.51(D21) U7.52(D20) U7.53(D19) U7.54(D18) U7.55(D17) U7.56(D16) U7.57(D15) U7.58(D14) U7.60(GND) U7.61(D13) U7.62(D12) U7.72(IO_GND) U7.73(GND) U8.1(ADJ) U9.4(V-) U10.1(ADJ) U11.2(GND) USB1.4(GND) USB1.5(S1) USB1.6(S2) USB2.4(GND) USB2.5 USB2.6
1_8V: C60.1 C67.1 C68.1 C69.1 C70.1 C71.1 C72.1 C73.1 C74.1 C75.1 U6.16(CVDD1) U6.17(VP18OUT) U6.47(CVDD2) U6.77(DVDD1) U6.94(VDD1) U6.104(PLLVDD1) U6.105(PLLVDD2) U6.112(TXVDD) U6.117(RXVDD) U6.119(VDD2)
3_3V: C48.1 C49.1 C50.1 C51.1 C52.1 C53.1 C57.1 C61.1 R71.1 R73.1 R78.2 R79.2 R80.2 R81.2 R82.2 R83.2 R84.1 U6.18(PVDD1) U6.50(PVDD2) U6.51(V33OUT) U6.66(AVDD1) U6.67(AVDD2) U6.73(AVDD3) U6.87(PVDD3) U6.88(VDD33SW) U6.91(VDD33OSC)
AUX0: R43.2 U1.95(I2C-DATA/AUX0) U4.5(SDA) U7.44(CSDA)
AUX1: R42.2 U1.94(I2C-CLK/AUX1) U4.6(SCL) U7.43(CSCL)
AUX2: J1.5 R39.2 U1.93(SR33/XD_CD#/DRV_VBUS2/SIN/AUX2)
AUX3: J1.4 R29.2 U1.72(SR34/SM_CD#/DRV_VBUS1/SOUT/AUX3)
AUX4: R40.1 R44.1 U1.71(IR/AUX4)
AUX7: J1.3 R135.2 U1.68(SR105/SM_CS#/XD_CS#/AUX7)
BANK0: R1.1 R2.1 U1.34(SR84/DBANK0) U5.20(BA0)
BANK1: R24.1 U1.27(SR83/DBANK1) U5.21(BA1)
C_DAC: C127.1 L6.2 R126.1 U1.80(SR92/CDAC/A-VR/A-VB)
CARD_VCC: C46.1 C47.1 CN1.5(VCC) CN6.12(VDD_SD) CN6.19(VCC_MS) Q2.3(D) R52.2 R53.2 R54.2 R55.2 R56.2 R134.2
CDPWR: Q2.1(G) R66.1 R131.1
CKE: R48.1 U5.37(CKE)
COUT: CN3.6(R) L7.1
CPUCLK: C3.1 R5.2 U1.146(XTAL_OUT) U1.172(SYSCLK) Y1.1
CS#: U1.61(SR85/DCS#) U5.19(~{CS})
CVBS1: CN4.6(R) L9.1
DB0: U1.35(DB[0]) U5.2(DQ0)
DB1: U1.36(DB[1]) U5.4(DQ1)
DB2: U1.37(DB[2]) U5.5(DQ2)
DB3: U1.38(DB[3]) U5.7(DQ3)
DB4: U1.50(DB[4]) U5.8(DQ4)
DB5: U1.51(DB[5]) U5.10(DQ5)
DB6: U1.52(DB[6]) U5.11(DQ6)
DB7: U1.53(DB[7]) U5.13(DQ7)
DB8: U1.23(DB[8]) U5.42(DQ8)
DB9: U1.24(DB[9]) U5.44(DQ9)
DB10: U1.25(DB[10]) U5.45(DQ10)
DB11: U1.26(DB[11]) U5.47(DQ11)
DB12: U1.28(DB[12]) U5.48(DQ12)
DB13: U1.29(DB[13]) U5.50(DQ13)
DB14: U1.32(DB[14]) U5.51(DQ14)
DB15: U1.33(DB[15]) U5.53(DQ15)
DCAS#: R10.1 R13.1 U1.60(PLL_SEL[3]/DCAS#) U5.17(~{CAS})
DE: R100.2 RN8.5 U7.80(DE)
DM: U6.71(DM) USB2.2(D-)
DMA0: U1.15(DMA[0]) U5.23(A0)
DMA1: U1.14(DMA[1]) U5.24(A1)
DMA2: U1.13(DMA[2]) U5.25(A2)
DMA3: U1.12(DMA[3]) U5.26(A3)
DMA4: U1.11(DMA[4]) U5.29(A4)
DMA5: U1.10(DMA[5]) U5.30(A5)
DMA6: U1.8(DMA[6]) U5.31(A6)
DMA7: U1.7(DMA[7]) U5.32(A7)
DMA8: U1.6(DMA[8]) U5.33(A8)
DMA9: R25.1 U1.5(DMA[9]) U5.34(A9)
DMA10: R20.1 R21.1 U1.54(DMA[10]) U5.22(A10)
DMA11: R18.1 R19.1 U1.55(DMA[11]) U5.35(A11)
DMACK: R83.1 U6.62(~{DMACK})
DMARQ: R87.2 U6.54(DMARQ)
DP: U6.72(DP) USB2.3(D+)
DQM: R3.1 R4.1 U1.49(PLL_SEL[0]/DQM) U5.15(DQML) U5.39(DQMH)
DRAS#: R8.1 R9.1 U1.59(PLL_SEL[2]/DRAS#) U5.18(~{RAS})
DSCK: R45.1 U1.173(DSCK)
DSCK0: C13.1 R45.2 U5.38(CLK)
DWE#: R6.1 R7.1 U1.16(PLL_SEL[1]/DWE#) U5.16(~{WE})
E_EN: D6.2 D7.2 D8.2 P4.7(ESATA-EN) R138.1
FL: C107.2 C110.1 CN4.5(L) R118.2
FR: C100.2 C104.1 CN4.7(COM) R113.2
GPIO2: R89.2 U6.55(GPIO2)
GPIO4: R88.2 U6.64(GPIO4)
H_RX+: C65.2 J4.6(H_RX+)
H_RX-: C64.2 J4.5(H_RX-)
H_TX+: C59.2 J4.2(H_TX+)
H_TX-: C62.2 J4.3(H_TX-)
HA0: U1.154(SR24/HA[0]/XD_CLE/SM_CLE/NAND_CLE) U6.79(DA0)
HA1: U1.155(SR25/HA[1]/XD_ALD/SM_ALE/NAND_ALE) U6.78(DA1)
HA2: U1.1(SR101/HA[2]) U6.81(DA2)
HCS1#: U1.4(SR104/HCS1#) U6.83(~{CS0})
HCS2#: R84.2 U1.3(SR103/HCS3#) U6.85(~{CS1})
HD0: R52.1 R59.1 RN1.2 U1.100(SR00/HD[0]/MS_D[0]/SD_D[0]/XD_D[0]/SM_D[0]/NAND_D[0])
HD1: R53.1 R60.1 RN1.4 U1.101(SR01/HD[1]/MS_D[1]/SD_D[1]/XD_D[1]/SM_D[1]/NAND_D[1])
HD2: R54.1 R61.1 RN2.2 U1.102(SR02/HD[2]/MS_D[2]/SD_D[2]/XD_D[2]/SM_D[2]/NAND_D[2])
HD3: R55.1 R63.1 RN2.4 U1.103(SR03/HD[3]/MS_D[3]/SD_D[3]/XD_D[3]/SM_D[3]/NAND_D[3])
HD4: RN3.2 U1.104(SR04/HD[4]/XD_D[4]/SM_D[4]/NAND_D[4])
HD5: RN3.4 U1.110(SR05/HD[5]/XD_D[5]/SM_D[5]/NAND_D[5])
HD6: RN4.2 U1.111(SR06/HD[6]/XD_D[6]/SM_D[6]/NAND_D[6])
HD7: RN4.4 U1.112(SR07/HD[7]/XD_D[7]/SM_D[7]/NAND_D[7])
HD8: RN4.3 U1.19(SR70/HD[8])
HD9: RN4.1 U1.20(SR71/HD[9])
HD10: RN3.3 U1.21(SR72/HD[10])
HD11: RN3.1 U1.22(SR73/HD[11])
HD12: RN2.3 U1.41(SR74/HD[12])
HD13: RN2.1 U1.42(SR75/HD[13])
HD14: RN1.3 U1.43(SR76/HD[14])
HD15: RN1.1 U1.44(SR77/HD[15])
HDMI_0: RN7.8 U1.89(SR50/B_OUT0/YUV[0]/HDMI_D[0])
HDMI_1: RN7.7 U1.90(SR51/B_OUT1/YUV[1]/HDMI_D[1])
HDMI_2: RN7.6 U1.91(SR52/B_OUT2/YUV[2]/HDMI_D[2])
HDMI_3: RN7.5 U1.92(SR53/B_OUT3/YUV[3]/HDMI_D[3])
HDMI_4: RN6.8 U1.98(SR54/B_OUT4/YUV[4]/HDMI_D[4])
HDMI_5: RN6.7 U1.99(SR55/B_OUT5/YUV[5]/HDMI_D[5])
HDMI_6: RN6.6 U1.105(SR56/B_OUT6/YUV[6]/HDMI_D[6])
HDMI_7: RN6.5 U1.106(SR57/B_OUT7/YUV[7]/HDMI_D[7])
HDMI_8: R128.2 RN5.8 U1.109(SR40/R_OUT0/CAMIN[0]/HDMI_D[8])
HDMI_9: R129.2 RN5.7 U1.113(SR41/R_OUT1/CAMIN[1]/HDMI_D[9])
HDMI_10: RN5.6 U1.114(SR42/R_OUT2/CAMIN[2]/HDMI_D[10])
HDMI_11: RN5.5 U1.115(SR43/R_OUT3/CAMIN[3]/HDMI_D[11])
HDMI_BCK: RN9.2 U1.163(SR64/G_OUT[4]/TBCK)
HDMI_CLK: R99.1 U1.170(SR66/G_OUT[6]/YUV_CLK)
HDMI_D0: RN7.1 U7.79(D0)
HDMI_D1: RN7.2 U7.78(D1)
HDMI_D2: RN7.3 U7.77(D2)
HDMI_D3: RN7.4 U7.76(D3)
HDMI_D4: RN6.1 U7.75(D4)
HDMI_D5: RN6.2 U7.70(D5)
HDMI_D6: RN6.3 U7.69(D6)
HDMI_D7: RN6.4 U7.68(D7)
HDMI_D8: RN5.1 U7.67(D8)
HDMI_D9: RN5.2 U7.65(D9)
HDMI_D10: RN5.3 U7.64(D10)
HDMI_D11: RN5.4 U7.63(D11)
HDMI_DE: RN8.4 U1.149(SR44/R_OUT4/CAMIN[4]/HDMI_ACT)
HDMI_HS: RN8.2 U1.150(SR45/R_OUT5/CAMIN[5]/HDMI_HS)
HDMI_MCLK: RN9.4 U1.162(SR63/G_OUT[3]/MCLK)
HDMI_TDS3: RN10.8 U1.156(SR47/R_OUT7/CAMIN[7]/TSD3)
HDMI_TSD0: RN10.5 U1.157(SR60/G_OUT[0]/TSD0)
HDMI_TSD1: RN10.6 U1.158(SR61/G_OUT[1]/TSD1)
HDMI_TSD2: RN10.7 U1.161(SR62/G_OUT[2]/TSD2)
HDMI_TWS: RN9.1 U1.169(SR65/G_OUT[5]/TWS)
HDMI_VS: RN8.3 U1.151(SR46/R_OUT6/CAMIN[6]/HDMI_VS)
HIORDY: R82.1 U1.127(SR21/HIORDY/NAND_RDY/XD_RDY/SM_RDY) U6.60(IORDY)
HIRQ: R81.1 R85.2 U1.2(SR102/HIRQ) U6.65(INTRQ)
HP_DET: C95.1 P1.19(HPD) R106.2 U7.18(HPD)
HRD#: U1.153(SR23/HRD#/XD_RD#/SM_RD#/NAND_RD#) U6.58(~{DIOR})
HRST#: R133.1 U1.69(SR106/HRST#/SD_WP#/SM_WP_OUT#/XD_WP#/AUX6) U6.127(~{AREST})
HS: R102.2 RN8.7 U7.1(HSYNC)
HSYNC: J5.2 R129.1
HWR#: U1.152(SR22/HWR#/XD_WR#/SM_WR#/NAND_WR#) U6.56(~{DIOW})
IDCK: R99.2 U7.66(IDCK)
IODD0: RN4.6 U6.44(DD0)
IODD1: RN4.8 U6.40(DD1)
IODD2: RN3.6 U6.36(DD2)
IODD3: RN3.8 U6.30(DD3)
IODD4: RN2.6 U6.26(DD4)
IODD5: RN2.8 U6.14(DD5)
IODD6: RN1.6 U6.10(DD6)
IODD7: R86.2 RN1.8 U6.6(DD7)
IODD8: RN1.7 U6.8(DD8)
IODD9: RN1.5 U6.12(DD9)
IODD10: RN2.7 U6.21(DD10)
IODD11: RN2.5 U6.28(DD11)
IODD12: RN3.7 U6.32(DD12)
IODD13: RN3.5 U6.38(DD13)
IODD14: RN4.7 U6.42(DD14)
IODD15: RN4.5 U6.46(DD15)
IR: IR1.3 R44.2
KEY_IN: C14.1 R46.2 U1.63(KEY_INPUT)
MCLK: C94.1 RN9.5 U7.6(MCLK)
MODE0: D7.1 Q4.3 R73.2 R74.1 U6.19(MOD0)
MODE1: D6.1 Q3.3 R71.2 U6.49(MODE1)
MS_CD#: CN6.15(INS_MS) R130.1 R131.2 U1.121(SR13/HD[11]/MS_CD#/PWM_VGH)
P+5V: C4.1 C131.1 C132.1 D4.1 D5.1 FB13.1 Q6.3(D) R26.2 R40.2 R41.2 R120.2 R136.1 U8.3(VIN)
PIO1: R80.1 U6.34(PIO1)
PIO2: R78.1 U6.57(PIO2)
PIO4: R79.1 U6.3(PIO4)
PWM_O1L: R115.1 U1.143(SR35/TWS/PWMO1_L/DAC_L)
PWM_O1R: R110.1 U1.144(SR36/TBCK/PWM_O1R/DAC_R)
RES: C63.2 D2.2 R93.1 R95.1
RESET: C66.1 D8.1 Q5.3 R94.2 U6.9(~{HRST})
RST#: C5.1 J3.5 Q1.3 R26.1 U1.56(RST#) U7.42(RESET#)
RTC_XIN: C8.1 R35.1 U1.130(RTC_XTAL_IN) Y2.1
RTC_XOUT: R35.2 R36.1 U1.131(RTC_XTAL_OUT)
RXN: C64.1 U6.115(RXN)
RXNEXT: P4.3(H_TX-) U6.108(RXNEXT)
RXP: C65.1 U6.116(RXP)
RXPEXT: P4.2(H_TX+) U6.107(RXPEXT)
SD_CD#: CN1.10(WP) CN6.1(CD_SD) R58.1 R66.2 U1.120(SR12/HD[10]/SD_CD#/PWM_VGL)
SD_CLK: CN1.6(CLK) CN6.9(CLK_SD) CN6.18(SCLK_MS) R64.2 R134.1
SD_CLK#: R64.1 U1.117(SR11/HD[9]/MS_CLK/SD_CLK)
SD_CMD: CN1.3(CMD) CN6.8(BS_MS) CN6.17(CMD_SD) R56.1 R65.2
SD_CMD#: R65.1 U1.116(SR10/HD[8]/MS_BS/SD_CMD)
SD_D0: CN1.8(D0) CN6.4(DAT0_SD) CN6.11(SDIO_MS) R59.2
SD_D1: CN1.9(D1) CN6.3(DAT1_SD) CN6.10(VCC_MS) R60.2
SD_D2: CN1.1(D2) CN6.13(RESERVED_MS) CN6.22(DAT2_SD) R61.2
SD_D3: CN1.2(D3) CN6.16(RESERVED_MS) CN6.20(CD/DAT3_SD) R63.2
SD_WP#: CN6.2(WP_SD) R132.1 R133.2
SPDIF: RN9.6 U7.5(SPDIF)
SPDIFO: RN9.3 U1.48(SPDIF_OUT/D-REV)
SPI_CS: J2.2 R31.1 R140.2 U2.1(CS#)
SPI_CS2#: J2.3 J3.1 U1.70(SR37/MUTE/NAND_CS#/SPI_CS2#/AUX5)
SPI_CS3: J2.1 R14.1 R15.1 R140.1 U1.66(SPI_CS3)
SPI_DI: J3.3 U1.64(SPI_DI) U2.2(DO)
SPI_DO: J3.4 U1.65(SPI_DO) U2.5(DI)
SPICLKD: C11.1 J3.2 R16.1 R17.1 U1.67(SPI_CLK) U2.6(CLK)
SR94: R32.1 U1.74(SR94/RSET)
T+5V: C97.1 FB13.2 P1.18(+5V) R107.1 R108.1
TBCK: RN9.7 U7.12(SCK)
TSD0: RN10.4 U7.10(SD0)
TSD1: RN10.3 U7.9(SD1)
TSD2: RN10.2 U7.8(SD2)
TSD3: RN10.1 U7.7(SD3)
TWS: RN9.8 U7.11(WS)
TX0+: P1.7(D0+) U7.30(TX0+)
TX0-: P1.9(D0-) U7.29(TX0-)
TX1+: P1.4(D1+) U7.33(TX1+)
TX1-: P1.6(D1-) U7.32(TX1-)
TX2+: P1.1(D2+) U7.36(TX2+)
TX2-: P1.3(D2-) U7.35(TX2-)
TX_SCL: P1.15(SCL) R107.2 U7.20(DSCL)
TX_SDA: P1.16(SDA) R108.2 U7.19(DSDA)
TXC+: P1.10(CLK+) U7.27(TXC+)
TXC-: P1.12(CLK-) U7.26(TXC-)
TXN: C62.1 U6.114(TXN)
TXNEXT: P4.5(H_RX-) U6.109(TXNEXT)
TXP: C59.1 U6.113(TXP)
TXPEXT: P4.6(H_RX+) U6.110(TXPEXT)
U_DAC: C125.1 L4.2 R125.1 U1.75(SR90/UDAC/A-VB/A-VR)
UOUT: CN3.5(L) L5.1
USB1_DN: R11.1 U1.135(USB1_DN)
USB1_DP: R12.1 U1.134(USB1_DP)
USB1_ID: R30.1 R33.2 U1.140(USB1_ID)
USB1_REF: R141.2 U1.137(USB1_RREF)
USB1_VB: R38.2 U1.139(USB1_VBUS)
USB2_DN: R22.1 U1.83(USB2_DN) USB1.2(D1-)
USB2_DP: R23.1 U1.82(USB2_DP) USB1.3(D1+)
USB2_ID: R34.1 R37.2 U1.88(USB2_ID)
USB2_REF: R142.2 U1.85(USB2_RREF)
USB2_VB: C1.1 FB1.2 U1.87(USB2_VBUS) USB1.1(VBUS)
USB_DET: R91.1 R92.2 U6.1(GPIO0)
V_DAC: C129.1 L8.2 R127.1 U1.76(SR96/VDAC/CVBS)
VC_USB1: C34.1 C35.1 FB7.2 U1.136(USB1_VCCA)
VC_USB2: C38.1 C39.1 FB9.2 U1.84(USB2_VCCA)
VCM: C115.1 R119.2 R121.1 U9.3(IN+) U9.5(IN+)
VD12: C15.1 C16.1 C17.1 C18.1 C19.1 C20.1 FB4.2 U1.30(VDD_1) U1.62(VDD_2) U1.97(VDD_3) U1.119(VDD_4) U1.159(VDD_5) U1.174(VDD_6)
VD33: C6.1 C21.1 C22.1 C23.1 C24.1 C25.1 C26.1 C27.1 FB2.2 U1.17(VD33_1) U1.39(VD33_2) U1.57(VD33_3) U1.108(VD33_4) U1.128(VD33_5) U1.147(VD33_6) U1.175(VD33_7) U3.2(VOUT) U3.4(Vout)
VD_DAC: C30.1 C31.1 FB5.2 U1.77(VD33_VDAC)
VD_PLL: C28.1 C29.1 FB3.2 U1.141(VD33_PLL)
VD_USB1: C32.1 FB6.2 U1.138(USB1_VDDA)
VD_USB2: C36.1 FB8.2 U1.86(USB2_VDDA)
VS: R101.2 RN8.6 U7.2(VSYNC)
VSYNC: J5.1 R128.1
X1: C55.1 R75.2 U6.93(X1) Y3.2
X2: C54.1 R75.1 U6.92(X2) Y3.1
XIN: C2.1 R5.1 U1.145(XTAL_IN) Y1.2
Y_DAC: C119.1 L1.2 R122.1 U1.79(SR95/YDAC/A-VG/A-VG)
YOUT: CN3.7(COM) L2.1
N01201: R46.1 R47.2 S1.1
N01207: R47.1 R49.2 S2.1
N01212: R49.1 R50.2 S3.1
N01239: R51.1 R57.2 S5.1
N01244: R50.1 R51.2 S4.1
N03440: R105.2 U7.21(TEST)
N03443: R103.1 R104.2 U7.41(CI2CA)
N03804: C82.1 C83.1 FB12.1 U7.38(PVCC2)
N03811: C79.1 C80.1 FB11.1 U7.23(PVCC1)
N03818: C76.1 C77.1 FB10.1 U7.28(AVCC) U7.34(AVCC)
N03841: R96.1 U7.24(EXT_SWING)
N03880: R97.1 R98.1 U7.59(VCC)
N04726: C105.1 C107.1 R114.2 U9.7(OUT2)
N04734: C105.2 R117.2 U9.6(IN-)
N04743: C106.1 C108.2 R115.2
N04745: C109.2 R114.1 R116.2 R117.1
N04760: C106.2 R116.1
N04770: C98.2 R112.2 U9.2(IN-)
N04773: C102.2 R109.1 R111.2 R112.1
N04775: C98.1 C100.1 R109.2 U9.1(OUT2)
N04782: C99.1 C101.2 R110.2
N04784: C99.2 R111.1
N04820: C126.1 L4.1 L5.2
N04822: C130.1 L8.1 L9.2
N04827: C128.1 L6.1 L7.2
N04850: C120.1 L1.1 L2.2
N51352: R57.1 R62.2 S6.1
N51356: R62.1 R67.2 S7.1 S7.3
N51360: R67.1 R68.2
N51364: R68.1 R69.2
N51633: R69.1 R70.2
N65349: C9.1 R36.2 Y2.2
N7534221: C4.2 D1.2 R27.1 R28.1
N11775686: Q1.1 R27.2
N13072366: R76.1 U6.96(RTREM)
N13086838: R77.1 U6.68(REFF)
N15489231: C12.1 IR1.1 R41.1
N16808105: Q6.1(G) Q7.3 R137.2
N16831810: C122.1 R123.2 R124.2 U11.5(VFB)
N16831812: D4.2 U3.3(VIN) U10.3(VIN)
N16831917: C124.1 D5.2 U11.1(Run) U11.4(VIN)
N16832146: L3.1 U11.3(SW)
N16953682: LED1.3 R90.1
N16953700: LED1.2 R89.1
N17431036: Q7.1 R138.2
N20916195: Q4.1 R72.2
N22082103: Q5.1 R93.2
N22349312: Q3.1 R74.2

Not connected (* = marked no-connect by the designer): CN6 24(CD_GND_SD); J4 8(3.3V) 9(3.3V) 10(3.3V) 18(GND) 20(12V) 21(12V) 22(12V) 23 24; P1 13(CEC)* 14(NC)*; P2 1(TP); P3 1(TP); RN8 1* 8*; U1 45(SD_CD#/RBCK/TDMCLK) 46(MS_CD#/RWS/TDMFS) 47(CF_CD#/RSD/TDMDR) 122(SR14/HD[12]/A-CPH2/D-LD/CF_CD#) 123(SR15/HD[13]/A-CPH3/D-POL) 124(SR16/HD[14]/A-VCOM/D-CKH) 125(SR17/HD[15]/A-CKV/D-CKV) 126(SR20/HIOCS16#/PWM_VLED) 129(RTC_GND) 132(RTC_BAT) 164(SR26/HA[2]/A-CPH1/D-PCLK0) 165(SR27/HIRQ/A-STH/D-STH) 166(SR30/HCS3#/A-STV/D-STV) 167(SR31/HCS1#/A-OEH/D-OEH) 168(SR32/HRST#/A-OEV/D-OEV) 171(SR67/G_OUT[7]/CAM_CLK); U5 36(NC)* 40(NC)*; U6 2(GPIO3) 4(PIO3) 5(ROM_A5) 7(ROM_A11) 11(ROM_A4) 13(ROM_A12) 15(ROM_A3) 22(ROM_A13) 24(TXD)* 25(RXD)* 27(ROM_A2) 29(ROM_A14) 31(ROM_A1) 33(PIO0) 35(ROM_A0) 37(ROM_D0) 39(ROM_D7) 41(ROM_D1) 43(ROM_D6) 45(ROM_D2) 53(ROM_D5) 61(GPIO1) 63(SPHYRDY)* 80(T_CPU)* 82(ROM_D3) 84(ROM_D4) 97(NC1)* 98(NC2)* 99(NC3)* 100(NC4)* 101(NC5)* 102(NC6)* 103(NC7)* 121(NEWPRE)* 122(ROM_A8) 123(ROM_A7) 124(ROM_A9) 125(ROM_A6) 126(ROM_A10) 128(SPDSEL)*; U7 17(INT)* 40(NC)*; USB1 7(P1)* 8(P2)*; Z1 1; Z2 1; Z4 1; Z5 1

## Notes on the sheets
sheet 1
- JUNE 5, 2008
- SICILY - DMP4 REFERENCE
- REVISION:  A2
- (176 PIN)
- POWER
- HISTORY
- PAGE
- NAME
- TYPE
- 4-15-08:
- 5-19-08:
- CHANGE SYSTEM POWER
- INITIAL DRAFT
- CHANGE RTC POWER CIRCUIT
- 1
- INDEX
- BREAK AWAY BOARD FOR EXTRA BUTTONS
- VD12
- DIGITAL 1.2V
- TERMINATION FOR ANALOG VIDEO
- VD33
- DIGITAL 3.3V
- 2
- DMP4 CONTROLLER
- VD_PLL
- ANALOG 3.3V
- 3
- SDRAM & NAND MEMORY
- VD_DAC
- ANALOG 3.3V
- VD_USB1
- ANALOG 1.2V
- 4
- MEMORY CARD CONNECTORS & LCD I/F
- VC_USB1
- ANALOG 3.3V
- 5
- HDMI TRANSMITTER & USB I/F
- VD_USB2
- ANALOG 1.2V
- GROUND
- VC_USB2
- ANALOG 3.3V
- 6
- A/V FILTERS & POWER
- +5V
- DIGITAL 5V
- NAME
- TYPE
- SYMBOL
- U1P
- DIGITAL 5V
- U2P
- DIGITAL 5V
- GND
- DIGITAL GROUND
- CFPWR
- DIGITAL 5V
- GNDA
- AUDIO GROUND
- CARD_VCC
- DIGITAL 3.3V
- GNDV
- VIDEO GROUND
- +3.3V_PLL
- ANALOG 3.3V
- PGND
- LCD GROUND
- PGND
- +5VA
- ANALOG 5V
- AGND
- RGB GROUND
- 5VIN
- DIGITAL 10V
- WGND
- PWM GROUND
- AGND
- WGND
- +1.8V
- DIGITAL 1.8V
- +3.3V
- DIGITAL 3.3V
- +1.2V
- DIGITAL 1.2V
- THE INFORMATION HAS BEEN CHECKED AND IS BELIEVED
  TO BE RELIABLE.  HOWEVER, NO RESPONSIBILITY IS
  ASSUMED FOR INNACCURACIES.  CIRCUIT DIAGRAMS ARE
  PROVIDED AS A MEANS OF ILLUSTRATING TYPICAL
  APPLICATIONS; CONSEQUENTLY COMPLETE INFORMATION
  FOR CONSTRUCTION PURPOSES IS NOT NECESSARILY
  GIVEN.  ESS RESERVES THE RIGHT TO MAKE CHANGES AT
  ANY TIME IN ORDER TO IMPROVE THE DESIGN.
sheet 2
- BOOT INT
- USB1 CONNECTORS
- PLL SEL[0]
- PLL SEL[1]
- PLL SEL[2]
- PLL SEL[3]
- BANK3 SEL
- INT RAM ROM
- BANK3 SERIAL
- 132
- 89
- PAGE SIZE SEL
- SPICLK SEL[1]
- 133
- 88
- SPICLK SEL[0]
- ESS
- DEBUG
- 176
- 45
- SRAM TEST
- 1
- 44
- PLACE NEAR
  ES6461
- SPI FLASH
- SPI EMUL
- SPI_CS2#
- RSET
- SPI FLASH
- EEPROM
sheet 3
- SDRAM
- KEYPAD INPUT
- SETUP
- SD_WP#
- MS_CD#
- SD_CD#
- EXIT
- RIGHT
- ENTER
- LEFT
- +3.3V
- DECOUPLING CAPACITORS
- DMP4
- +1.2V
- COPY
- SPI FLASH, RESET
- SDRAM
sheet 4
- Pin 16,47,77,94,104,105,112,117,119
sheet 5
- HDMI CONTROLLER
- STRAPPING FOR CI2CA
- Pull up   - I2C addresses 0x76 and 0x7E
- Pull down - I2C addresses 0x72 and 0x7A
- HDMI_ACT
- HDMI_VS
- HDMI_HS
- YUV_CLK
- +2.5V
- HDMI CONNECTOR
sheet 6
- AUDIO FILTER
- SOT-223
- VIDEO FILTERS
- (1.2V)
